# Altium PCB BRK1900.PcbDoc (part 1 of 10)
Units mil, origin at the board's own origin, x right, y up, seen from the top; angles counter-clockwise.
Board outline 8858.27 x 5905.51 mil, 10 copper layers (L1-TOP, L2-GND, L3-SIG1, L4-GND, L5-PWR, L6-PWR, L7-GND, L8-SIG2, L9-GND, L10-BOT), stack 48.824 mil thick; 507 components, 607 nets, 2498 pads, 2210 vias.
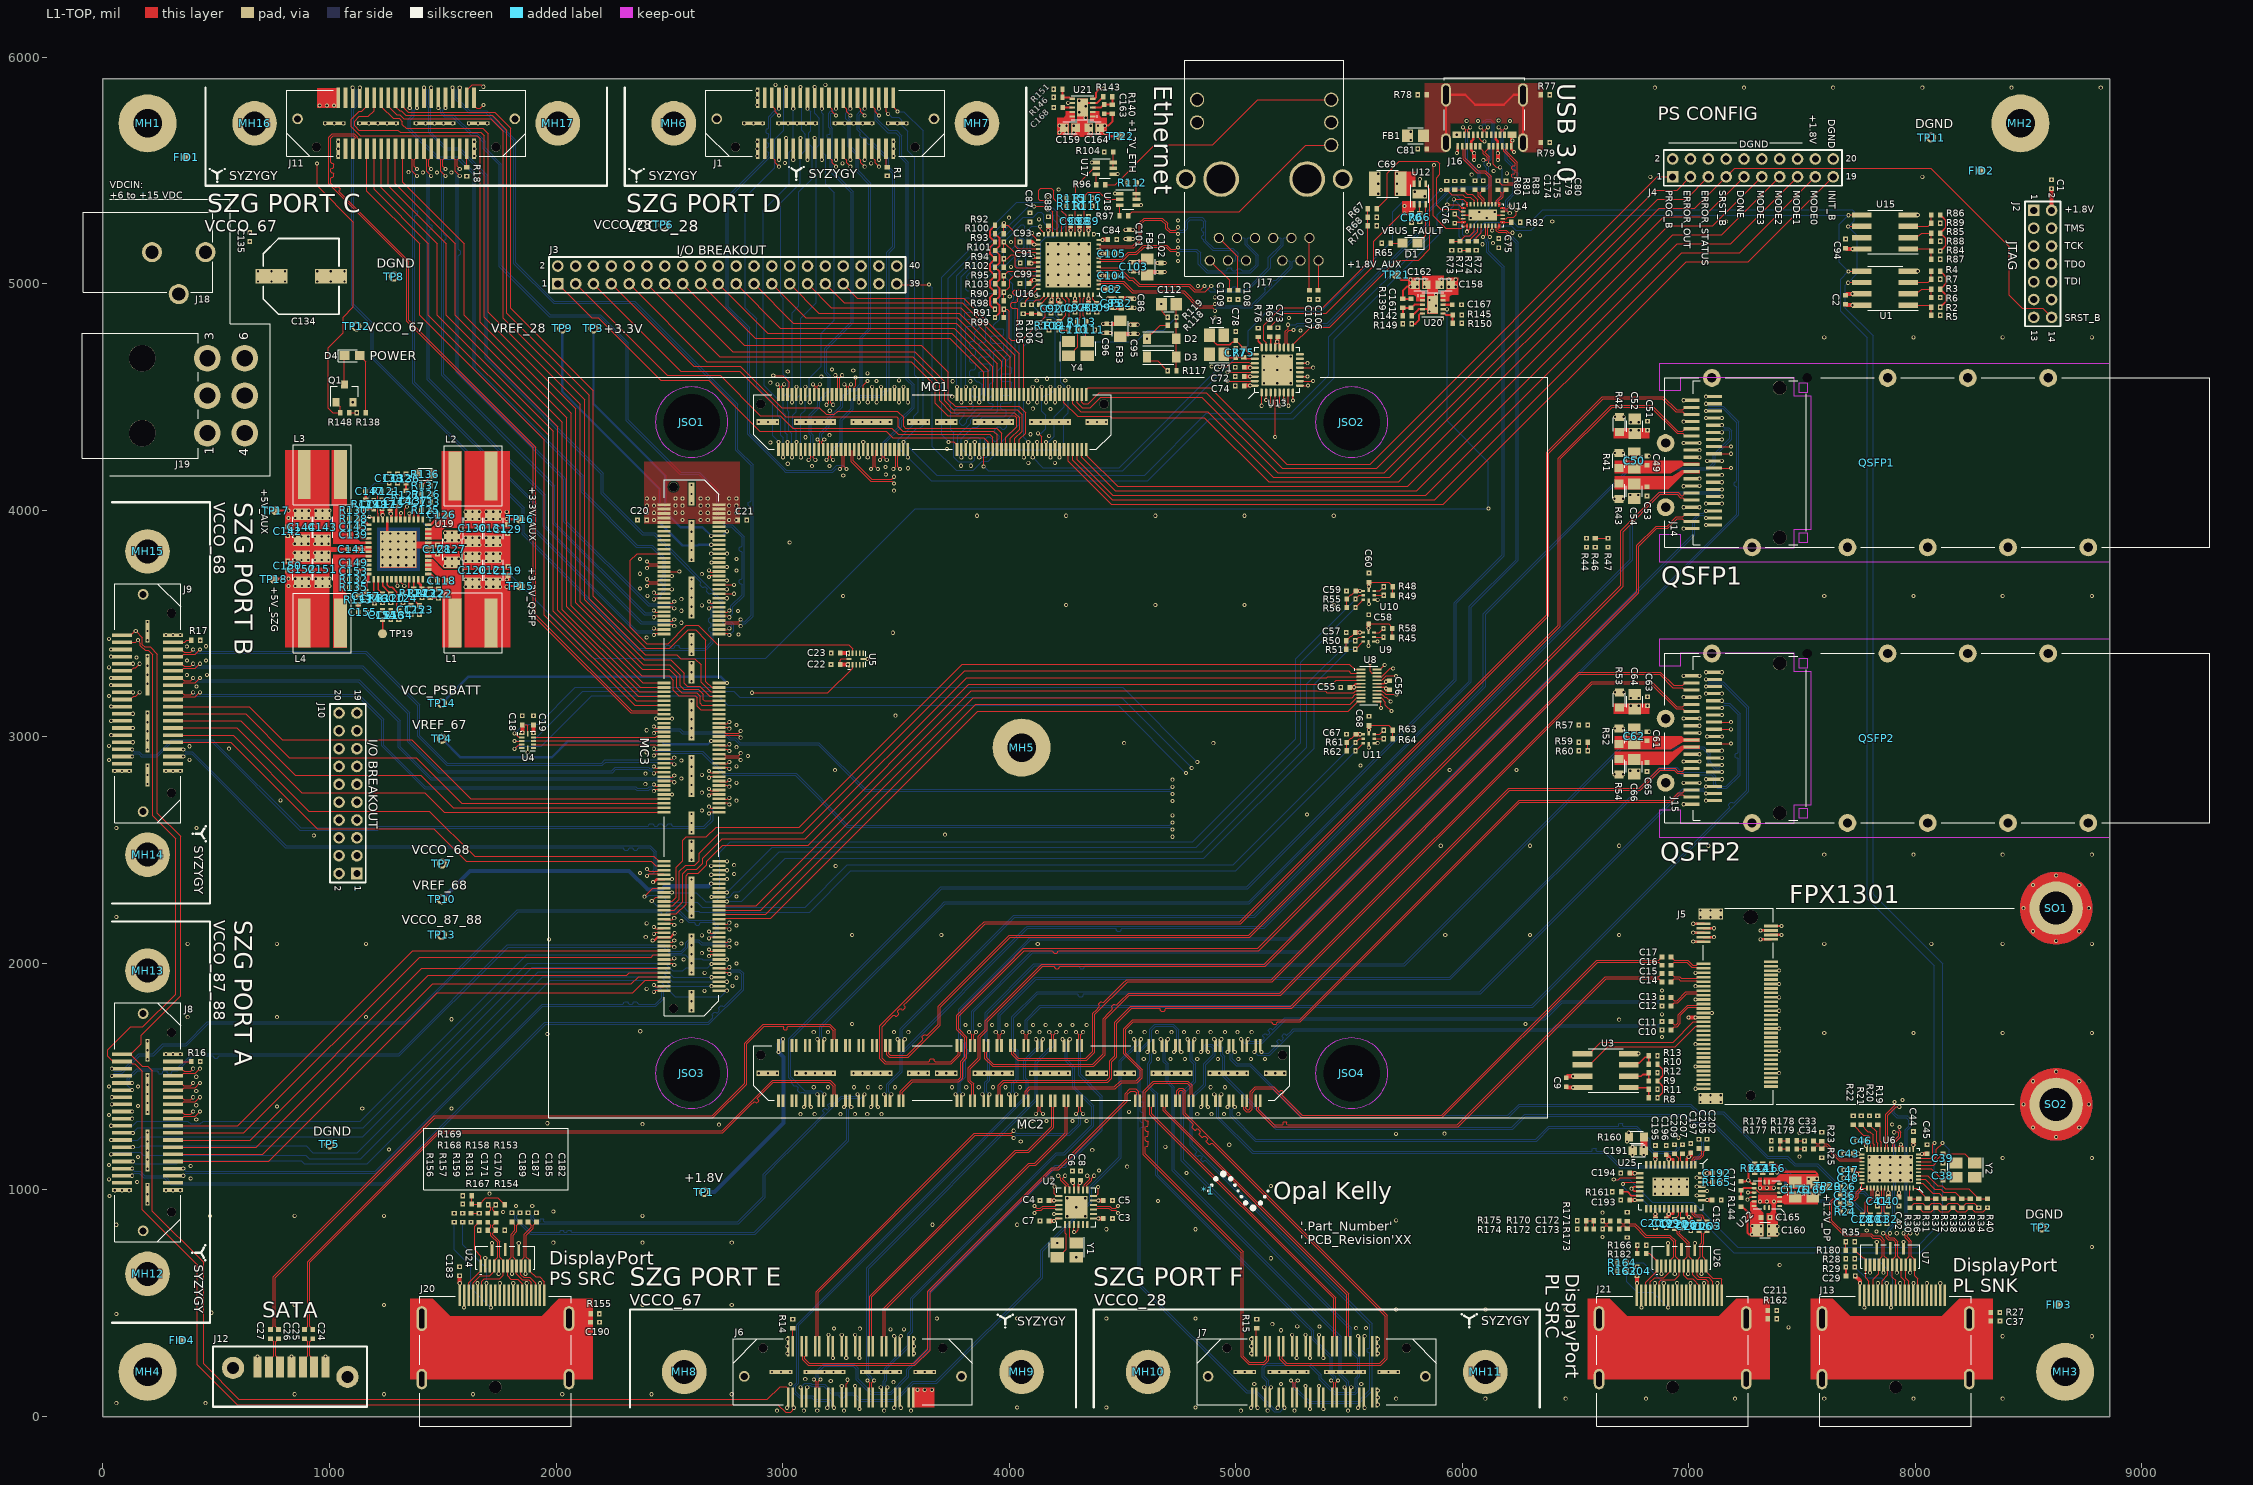
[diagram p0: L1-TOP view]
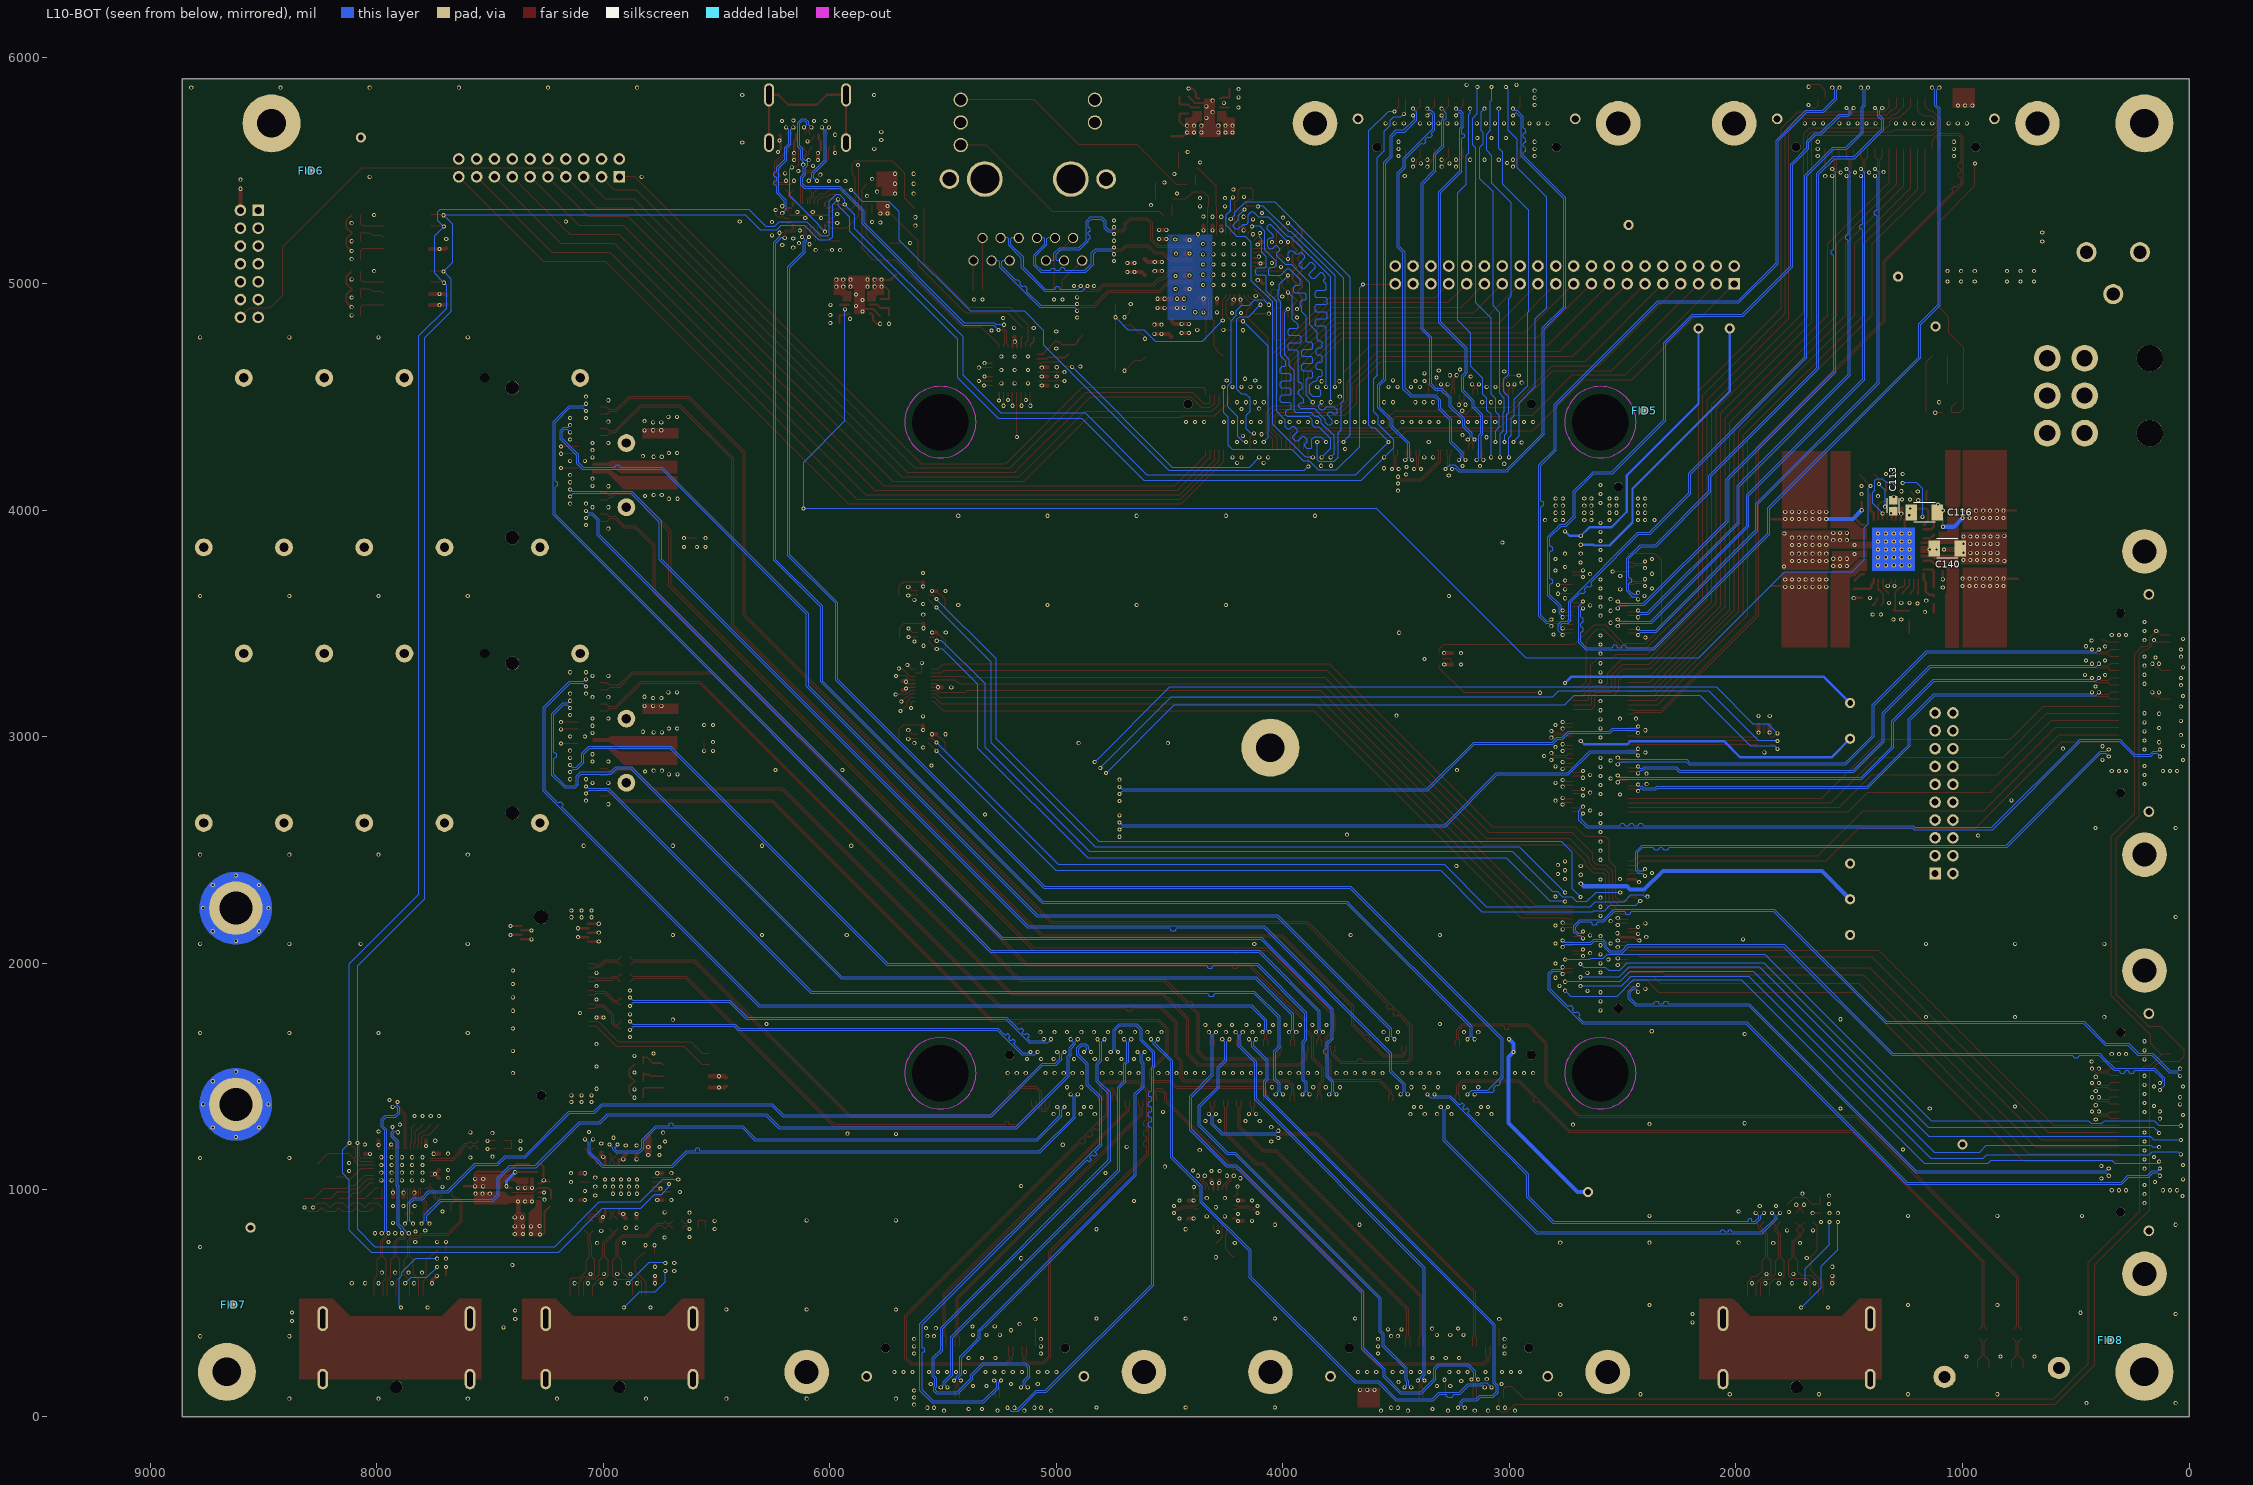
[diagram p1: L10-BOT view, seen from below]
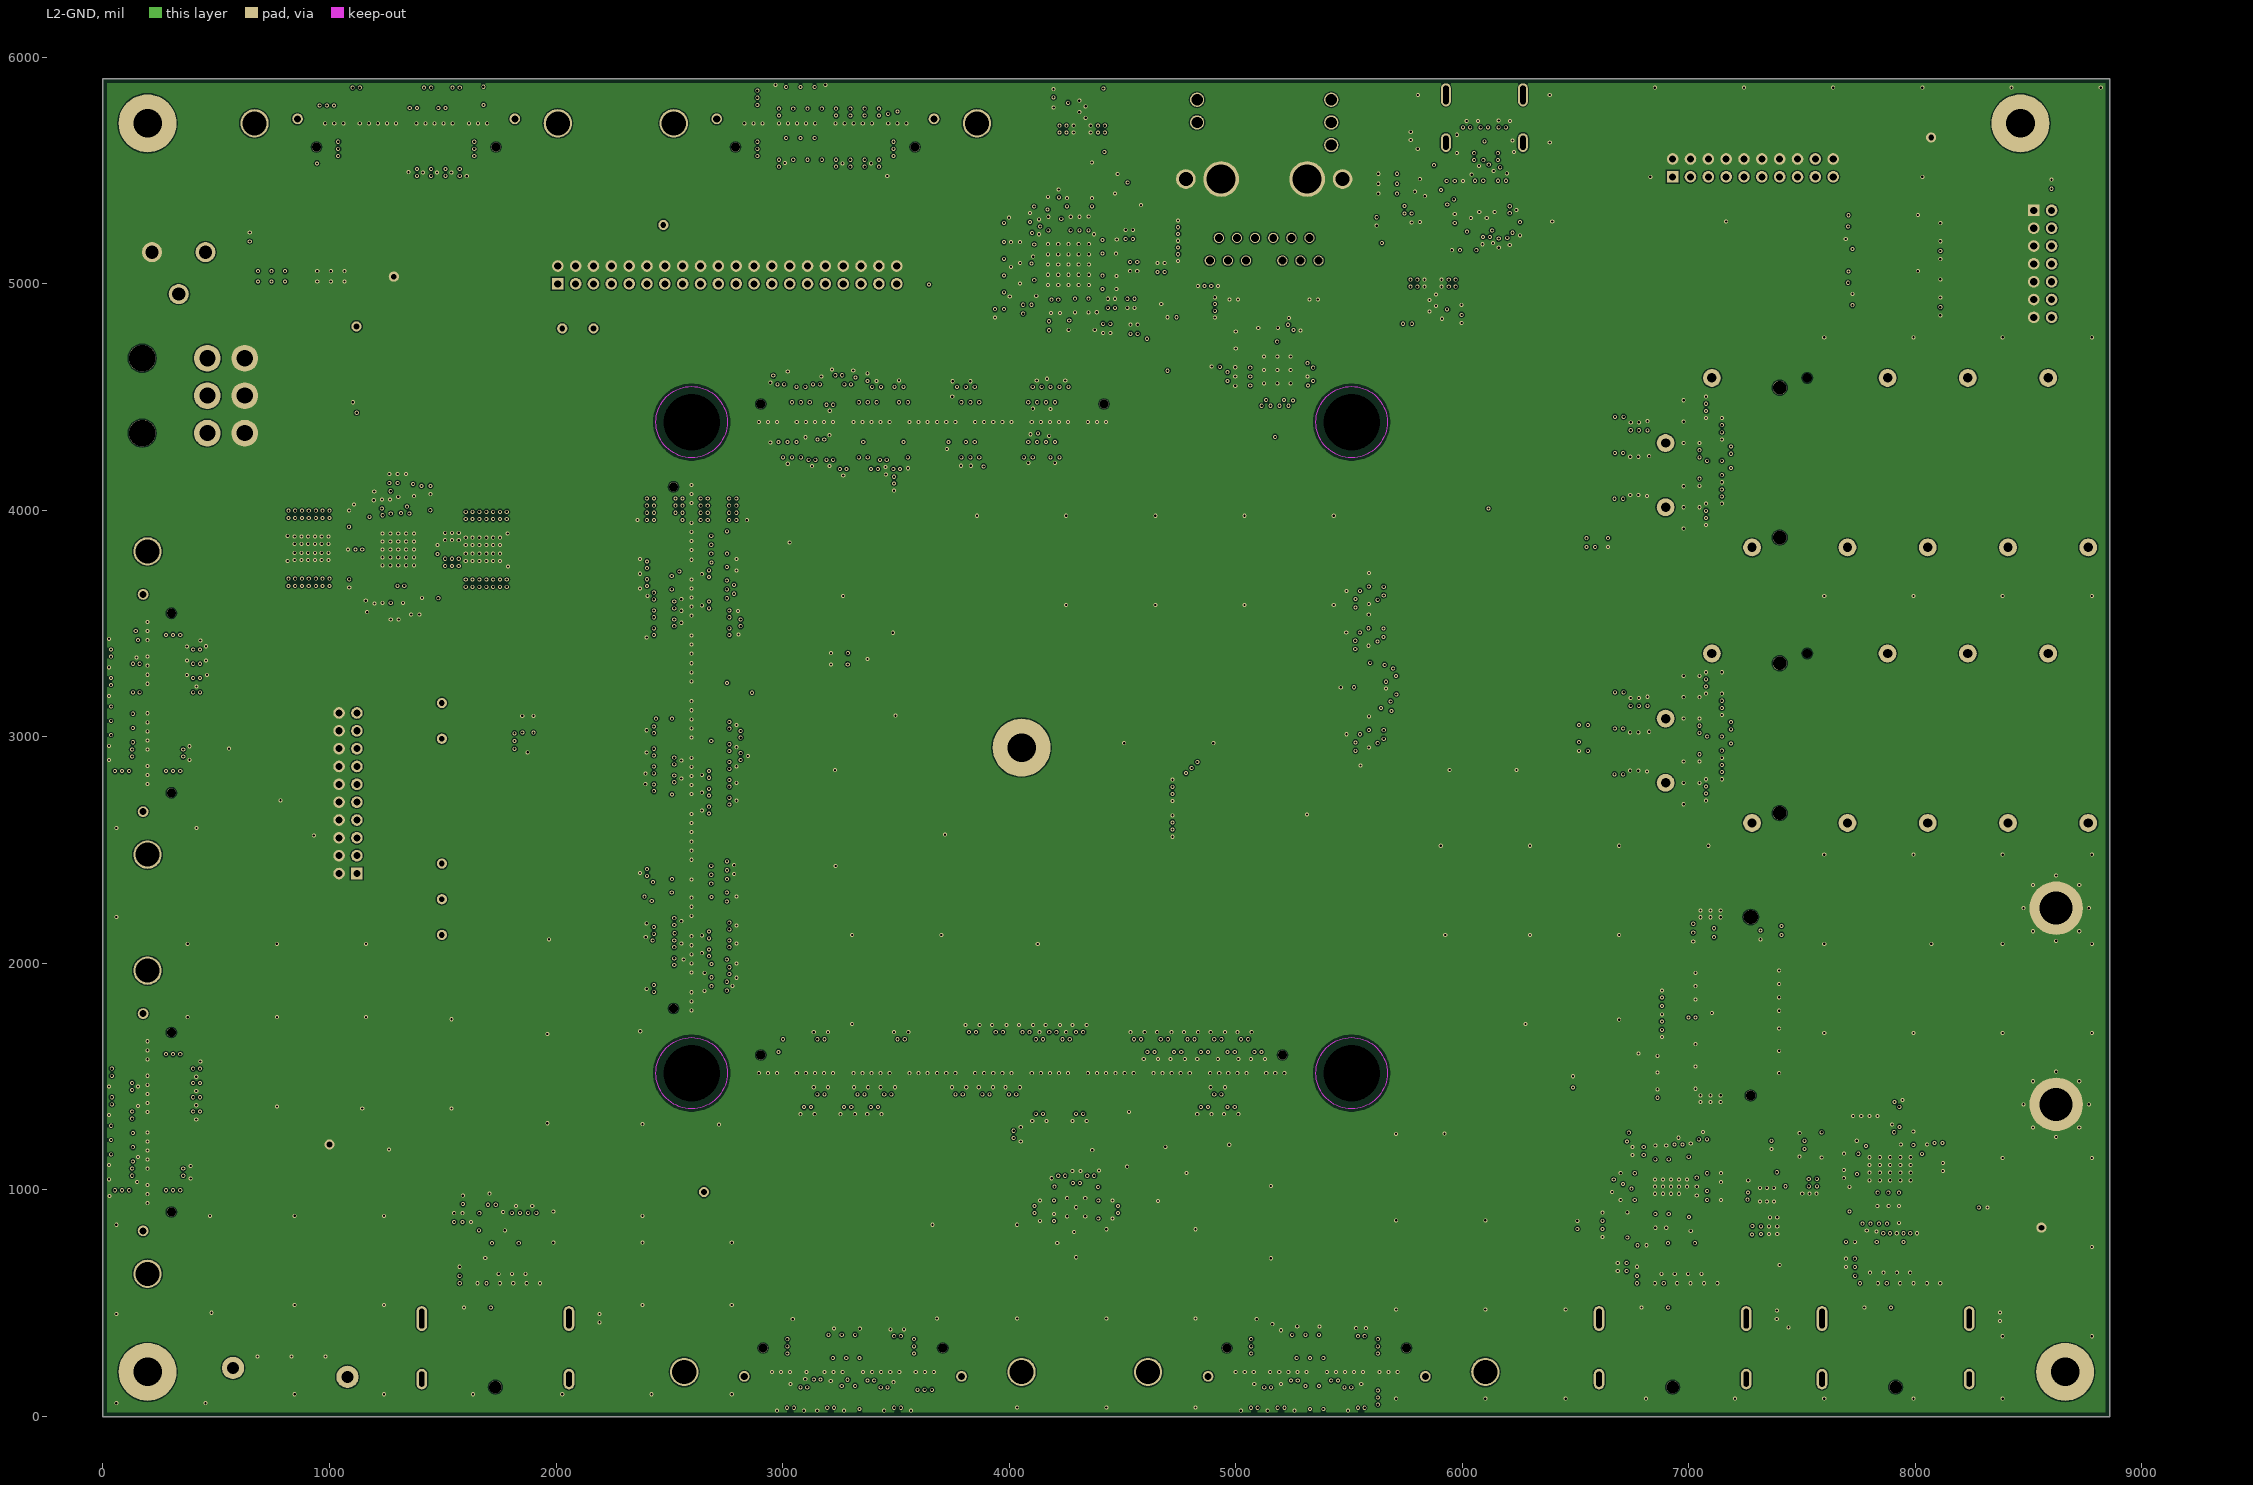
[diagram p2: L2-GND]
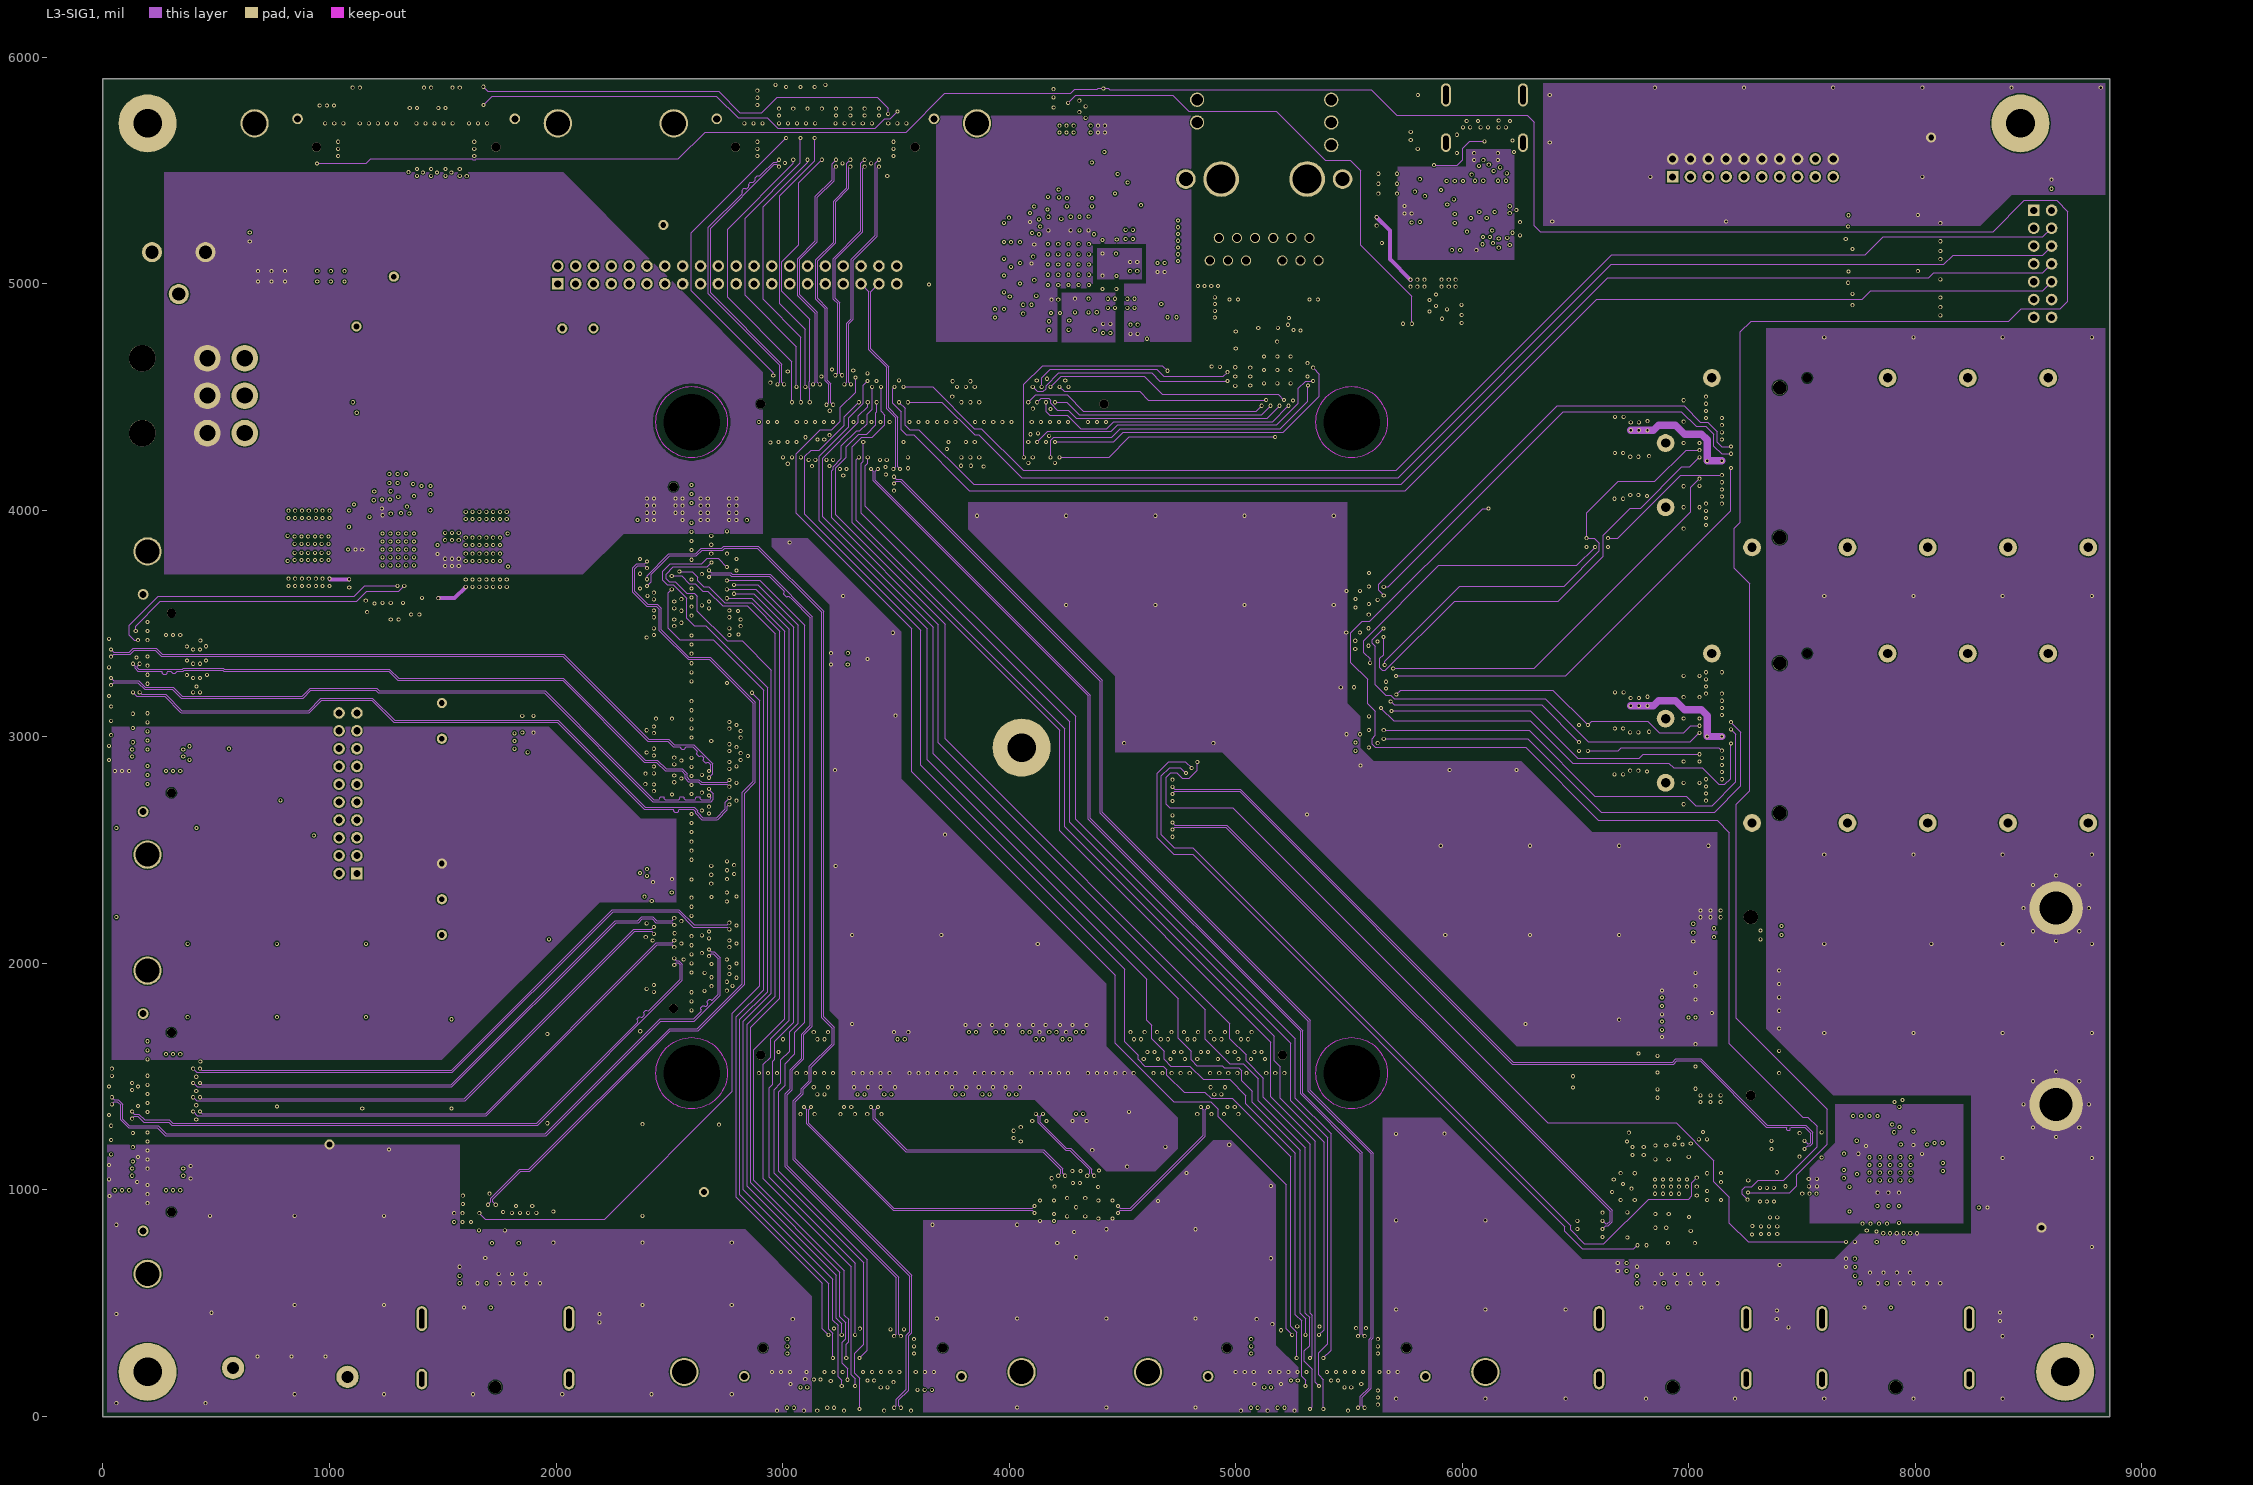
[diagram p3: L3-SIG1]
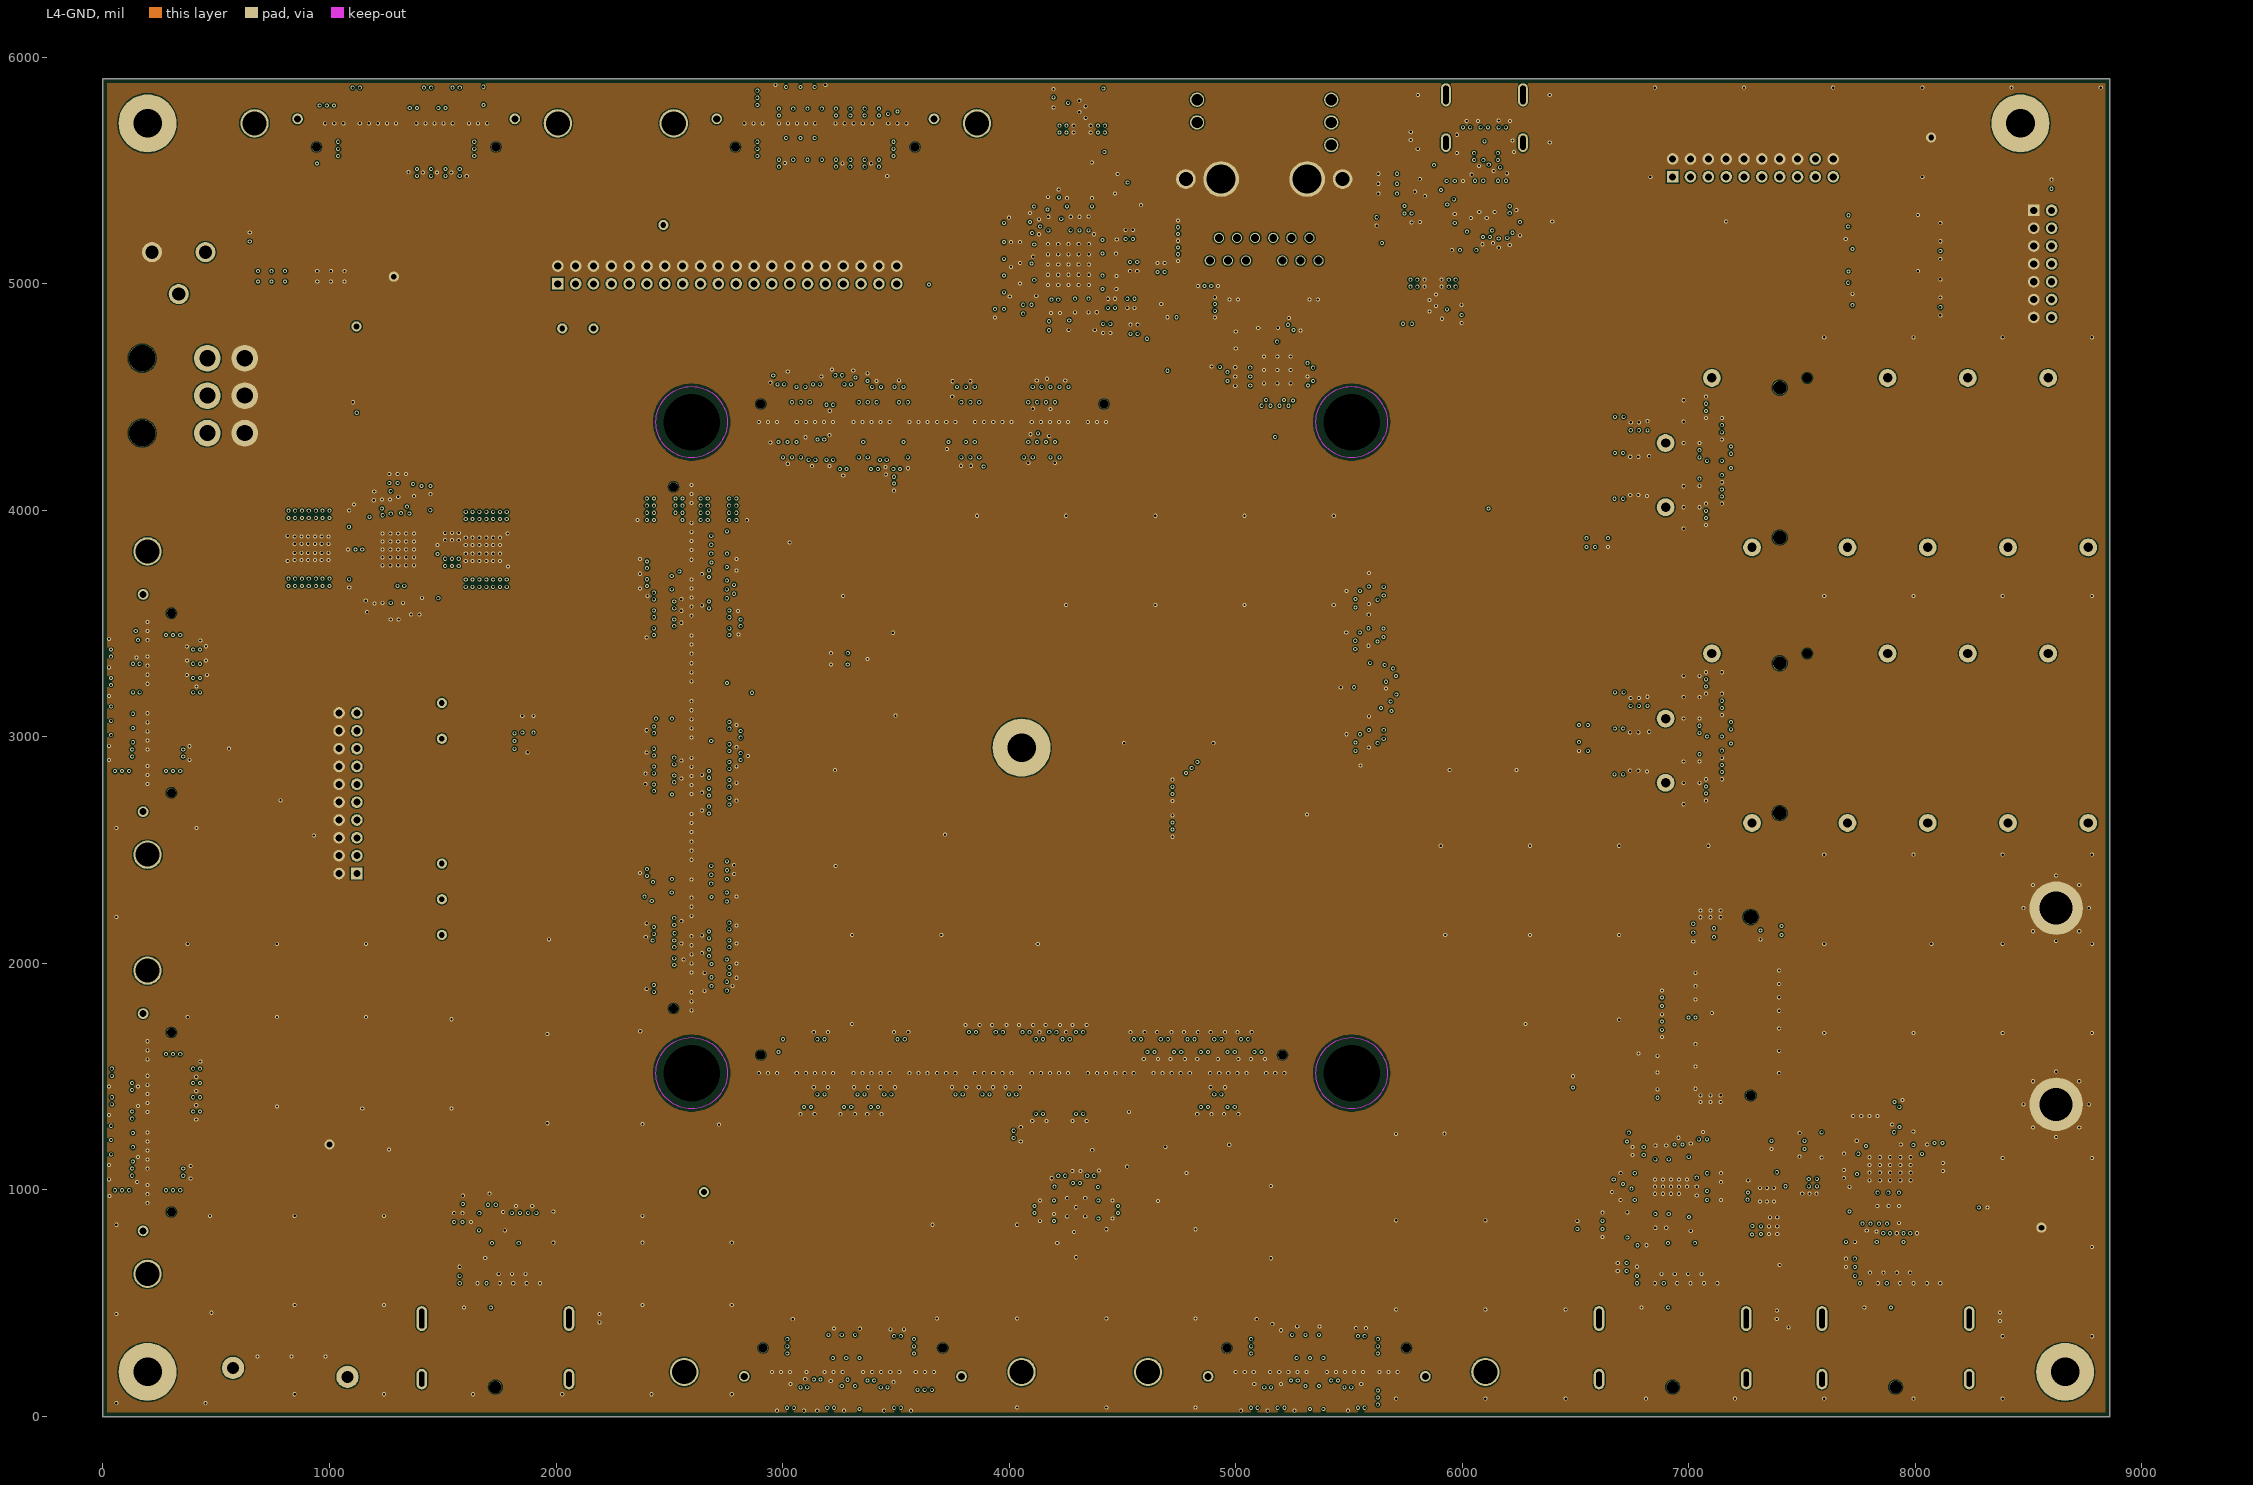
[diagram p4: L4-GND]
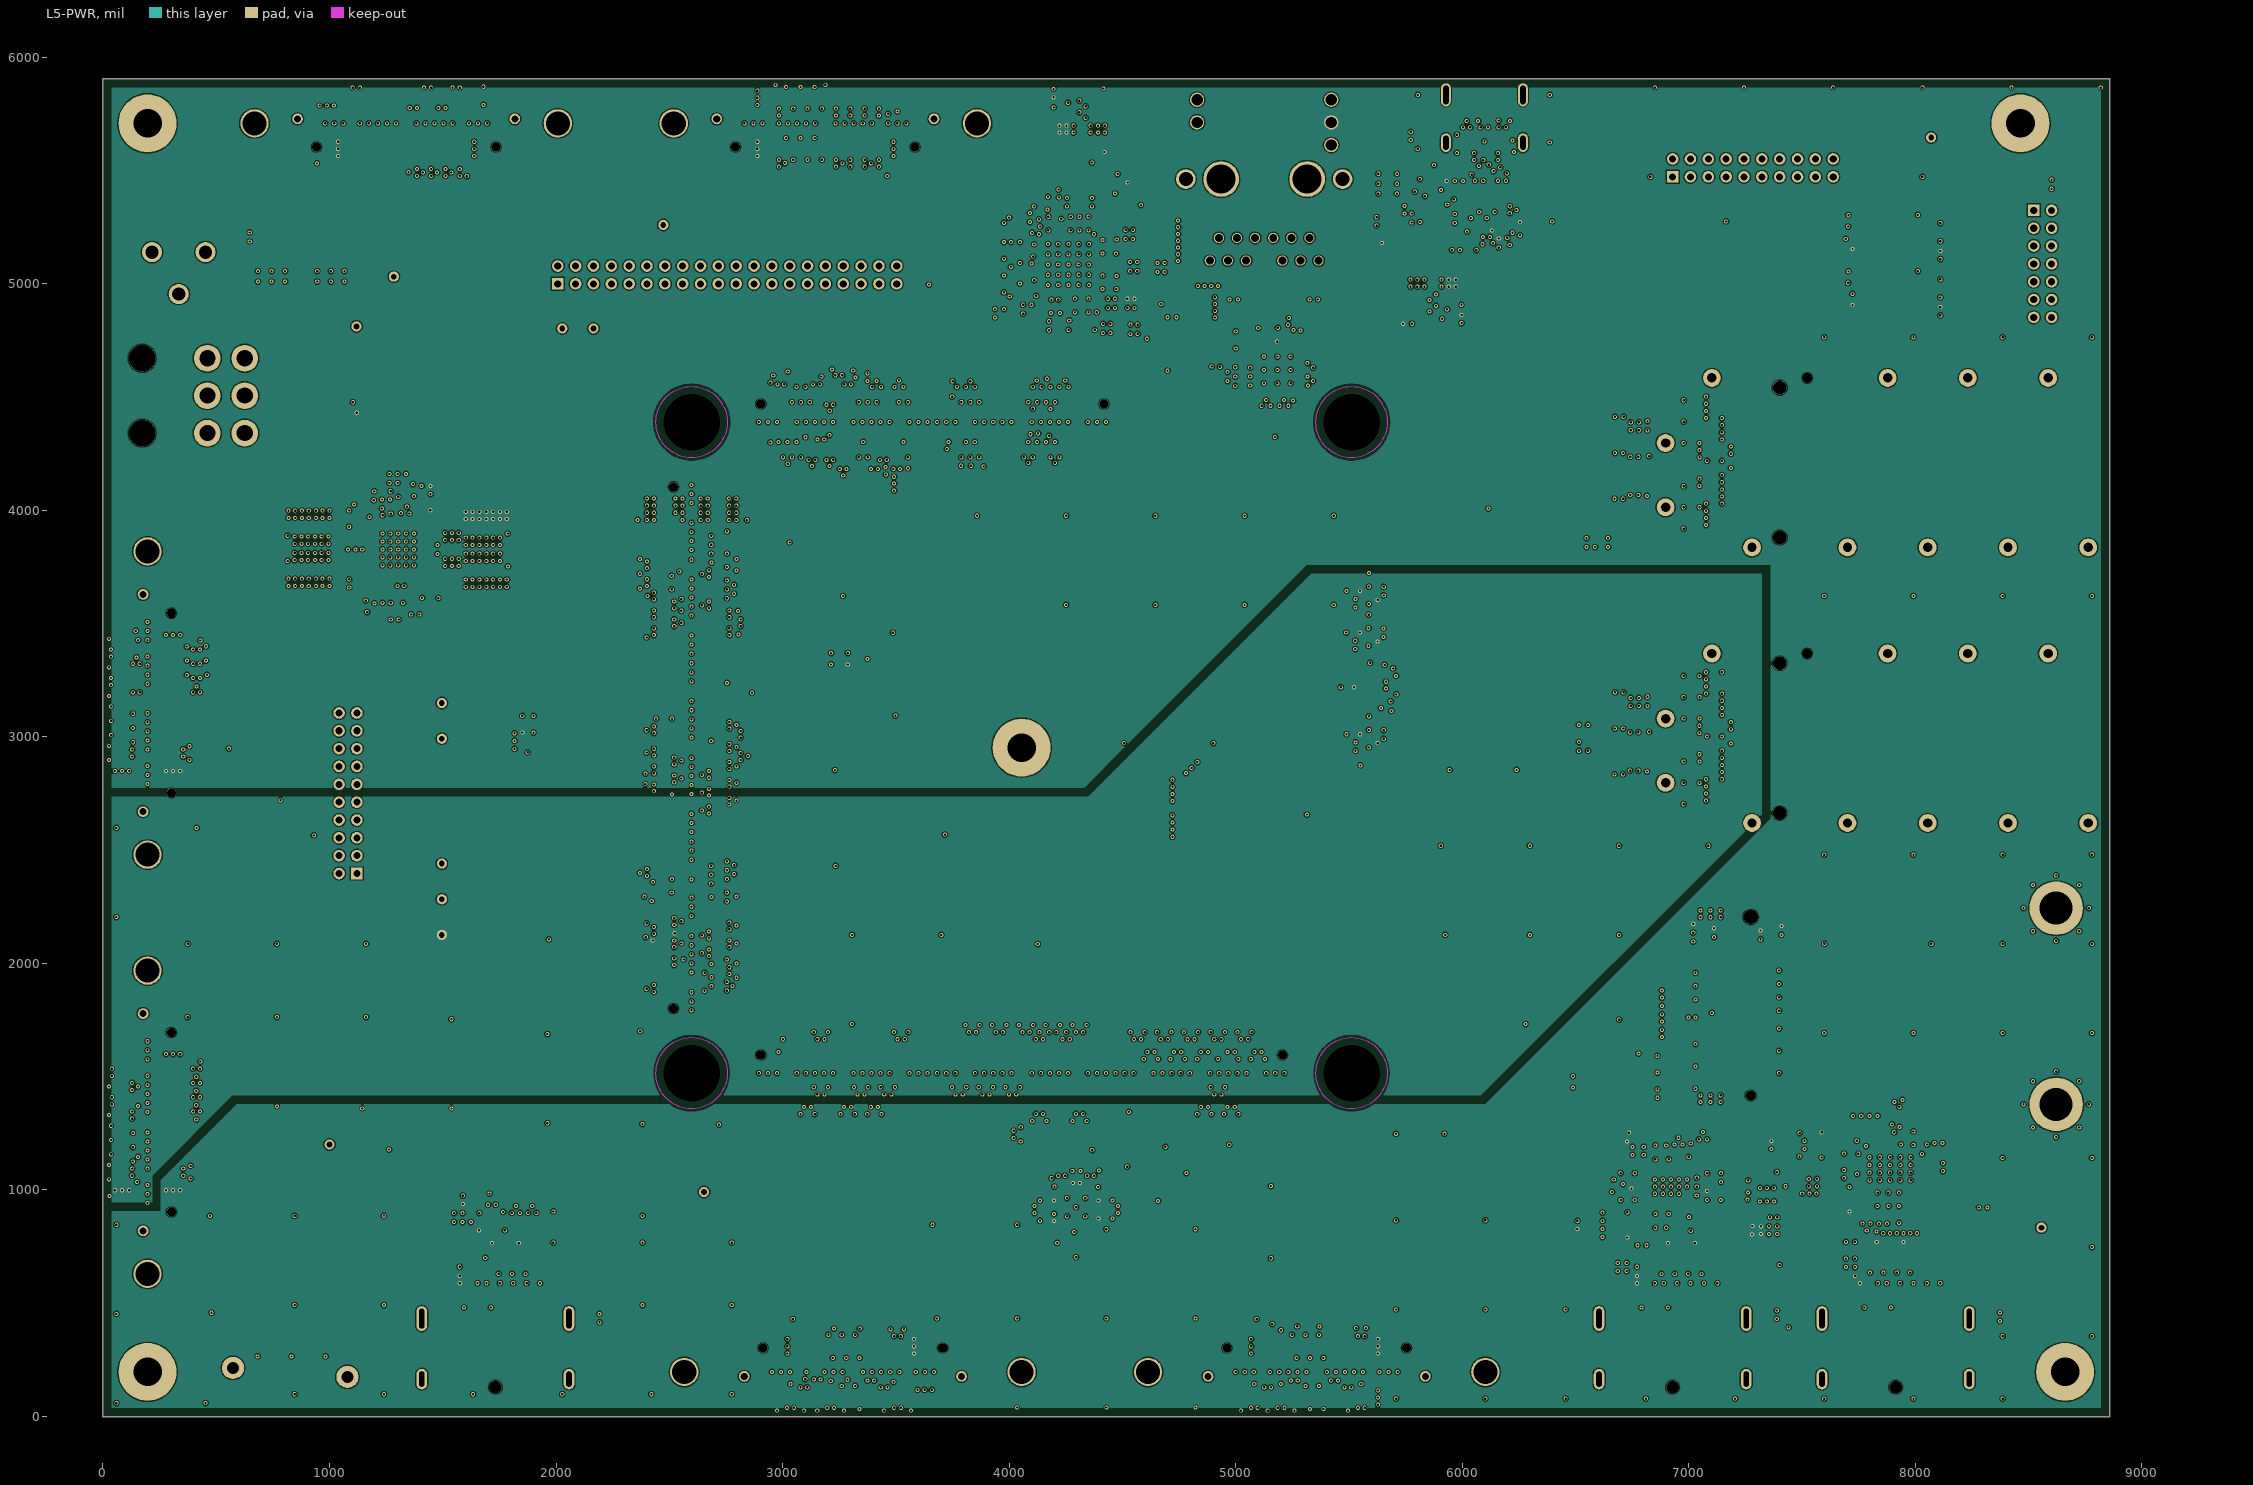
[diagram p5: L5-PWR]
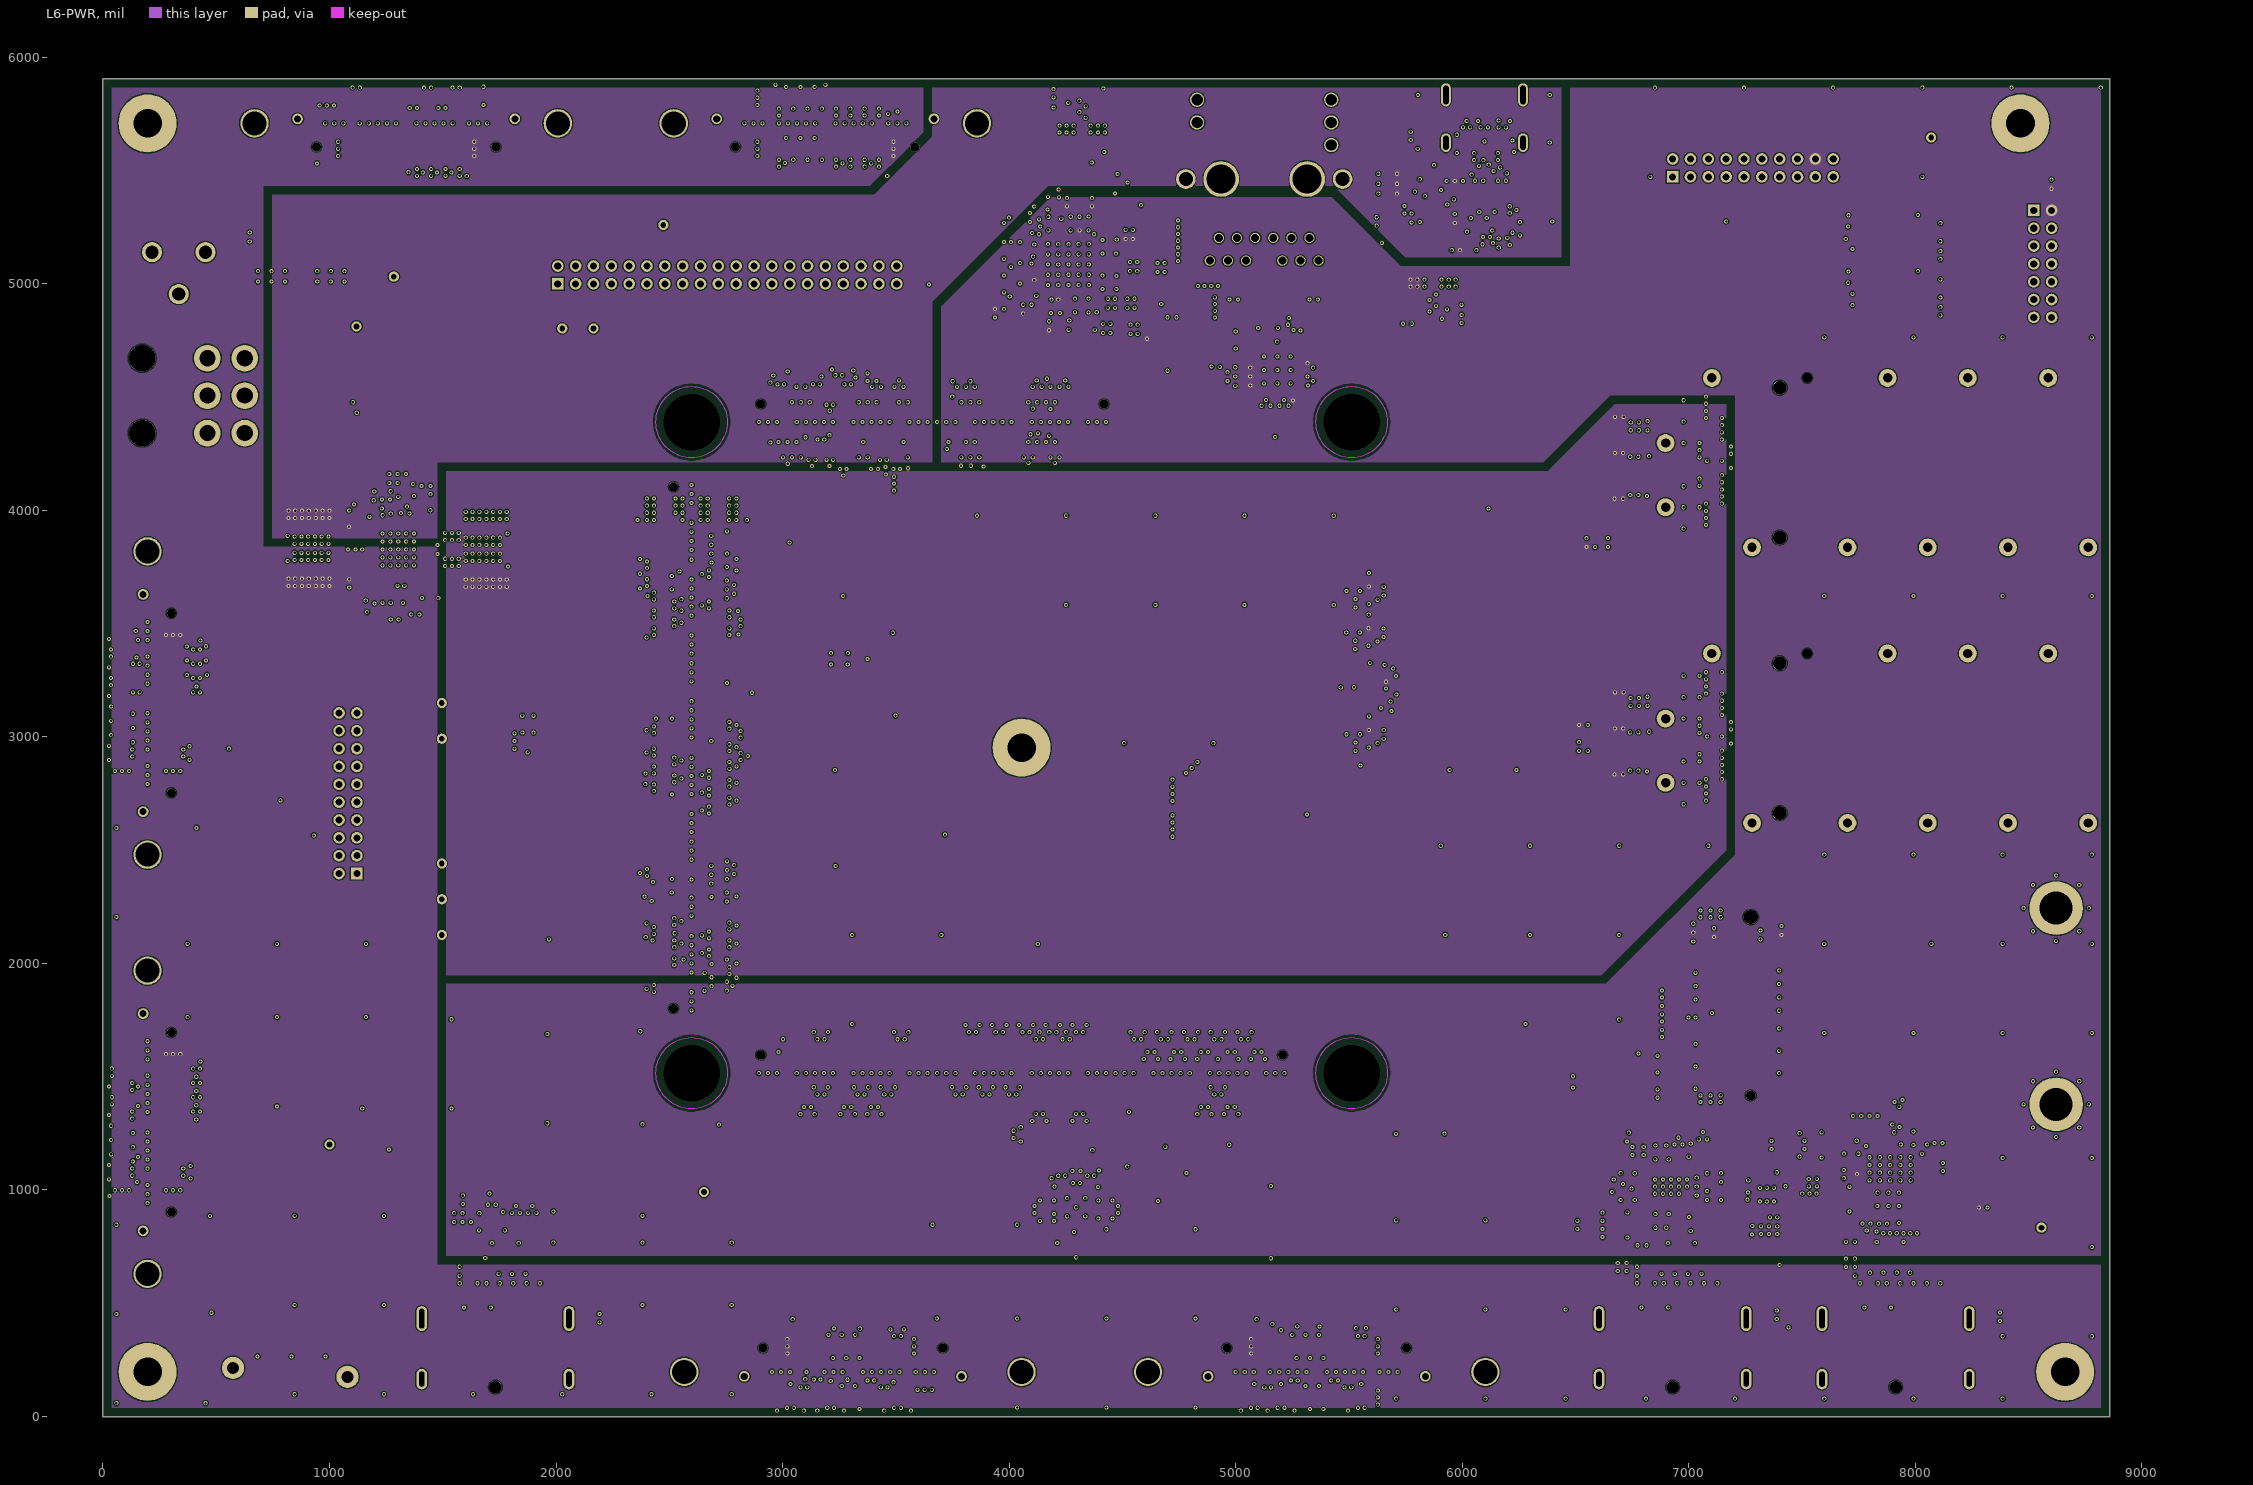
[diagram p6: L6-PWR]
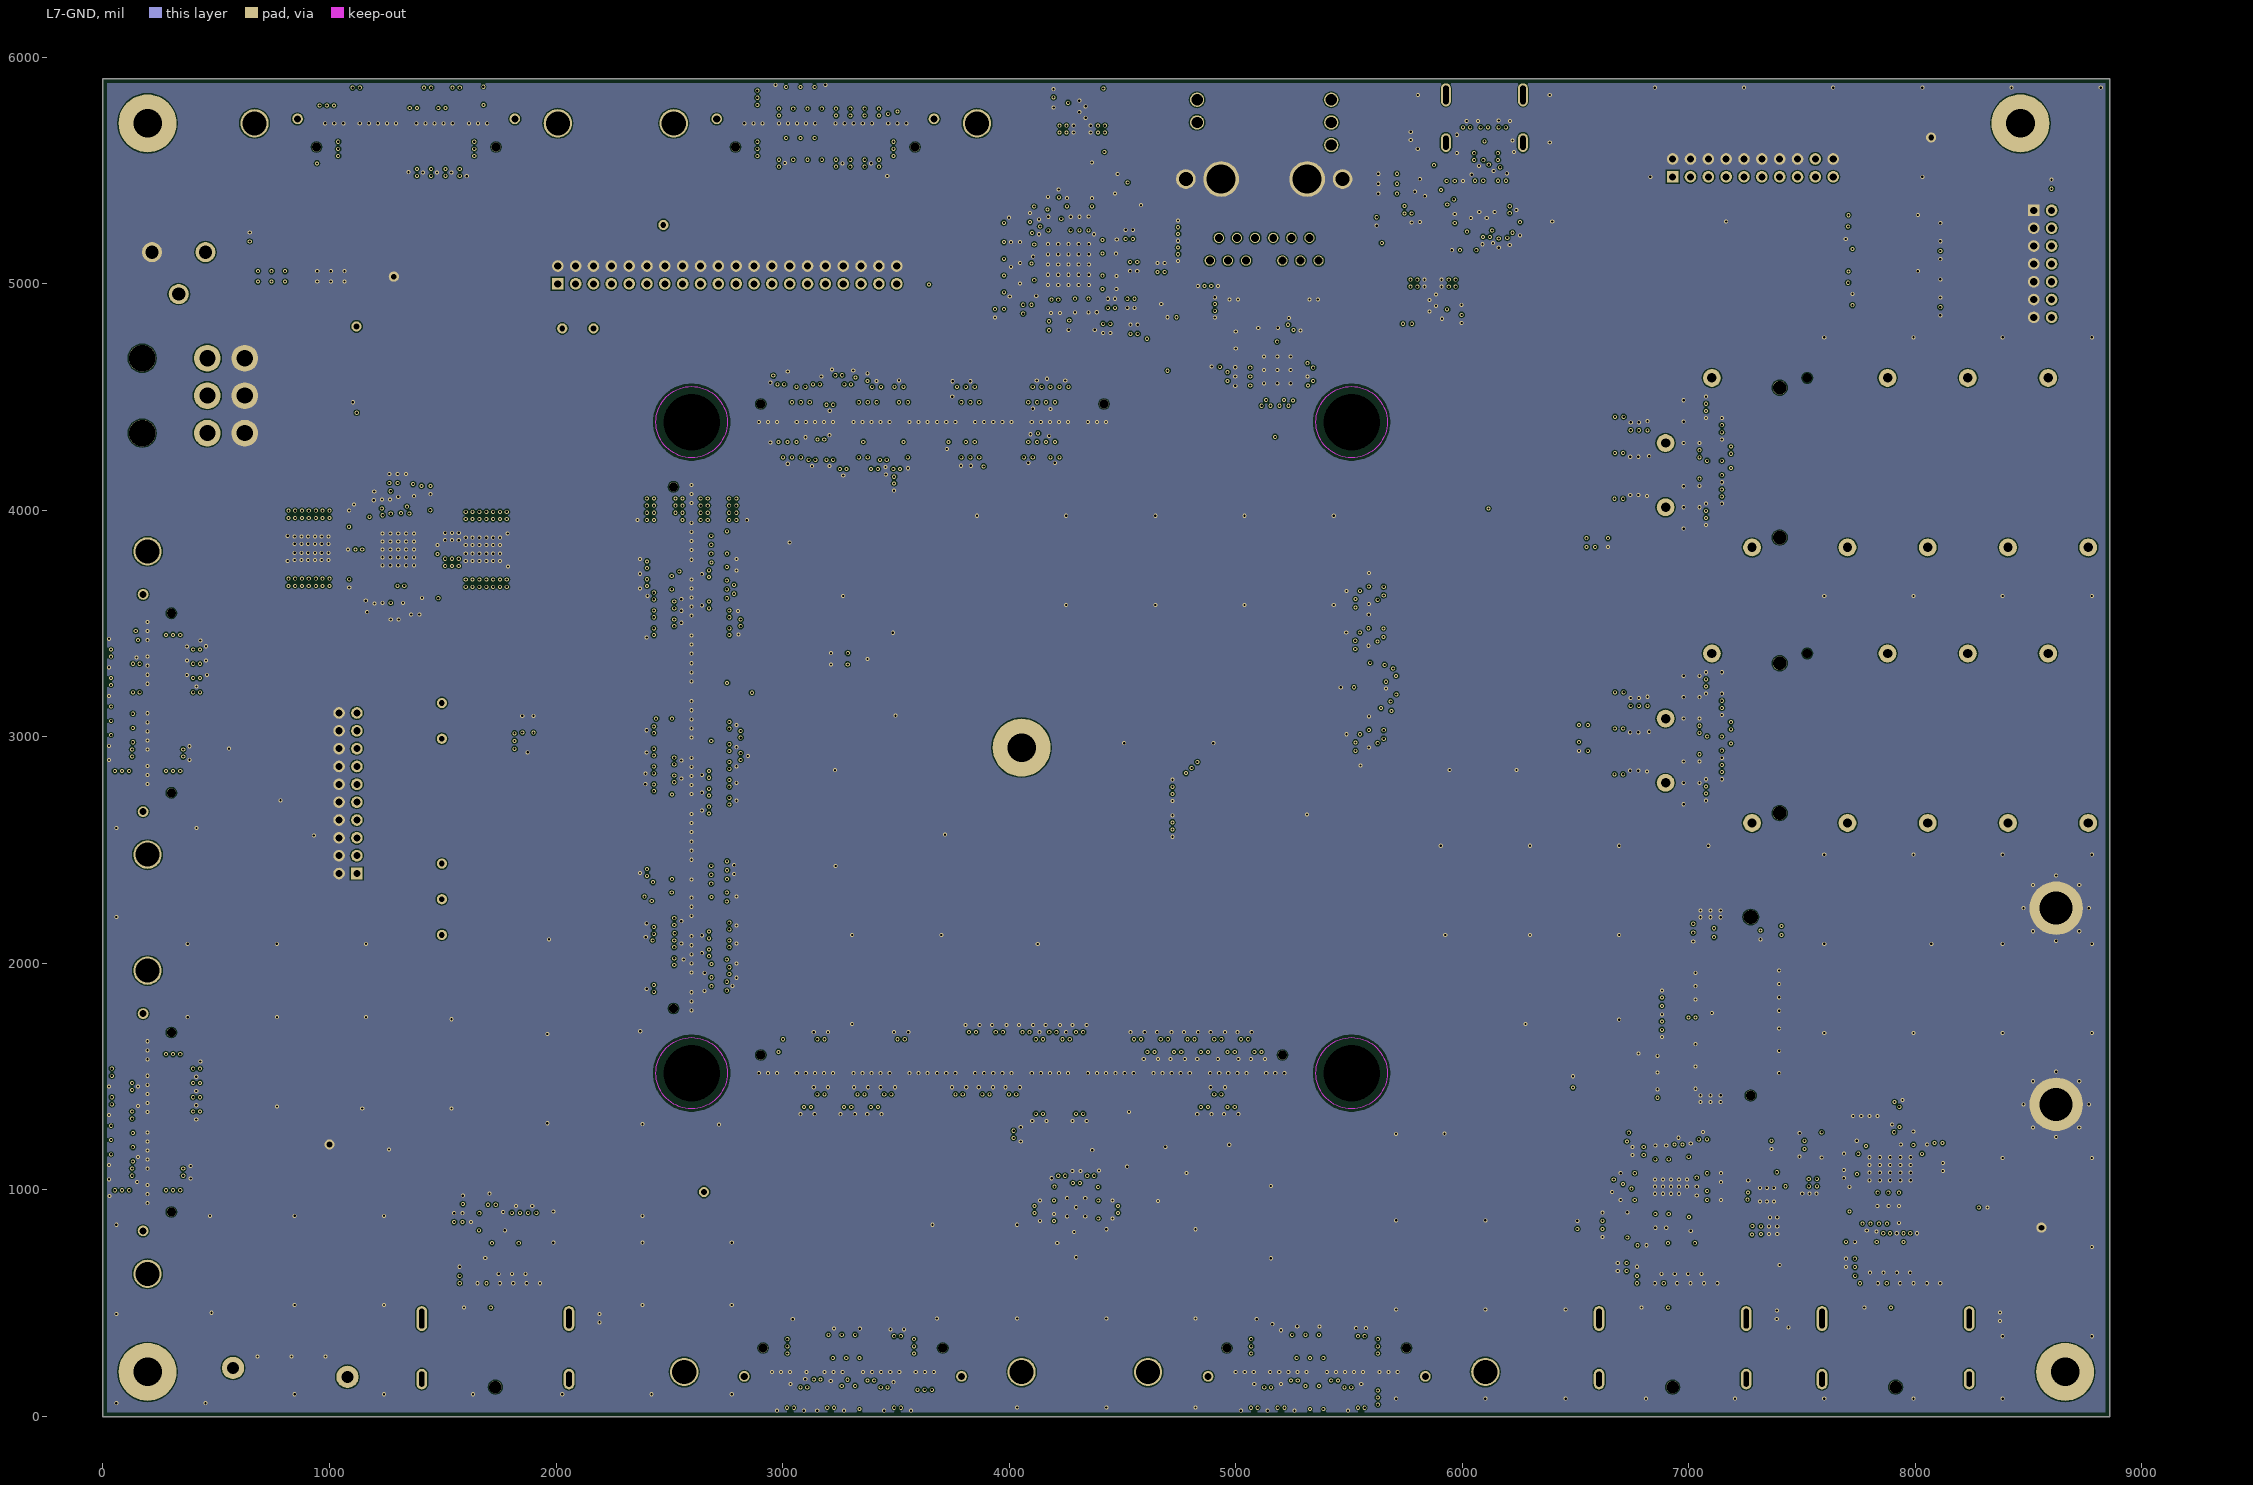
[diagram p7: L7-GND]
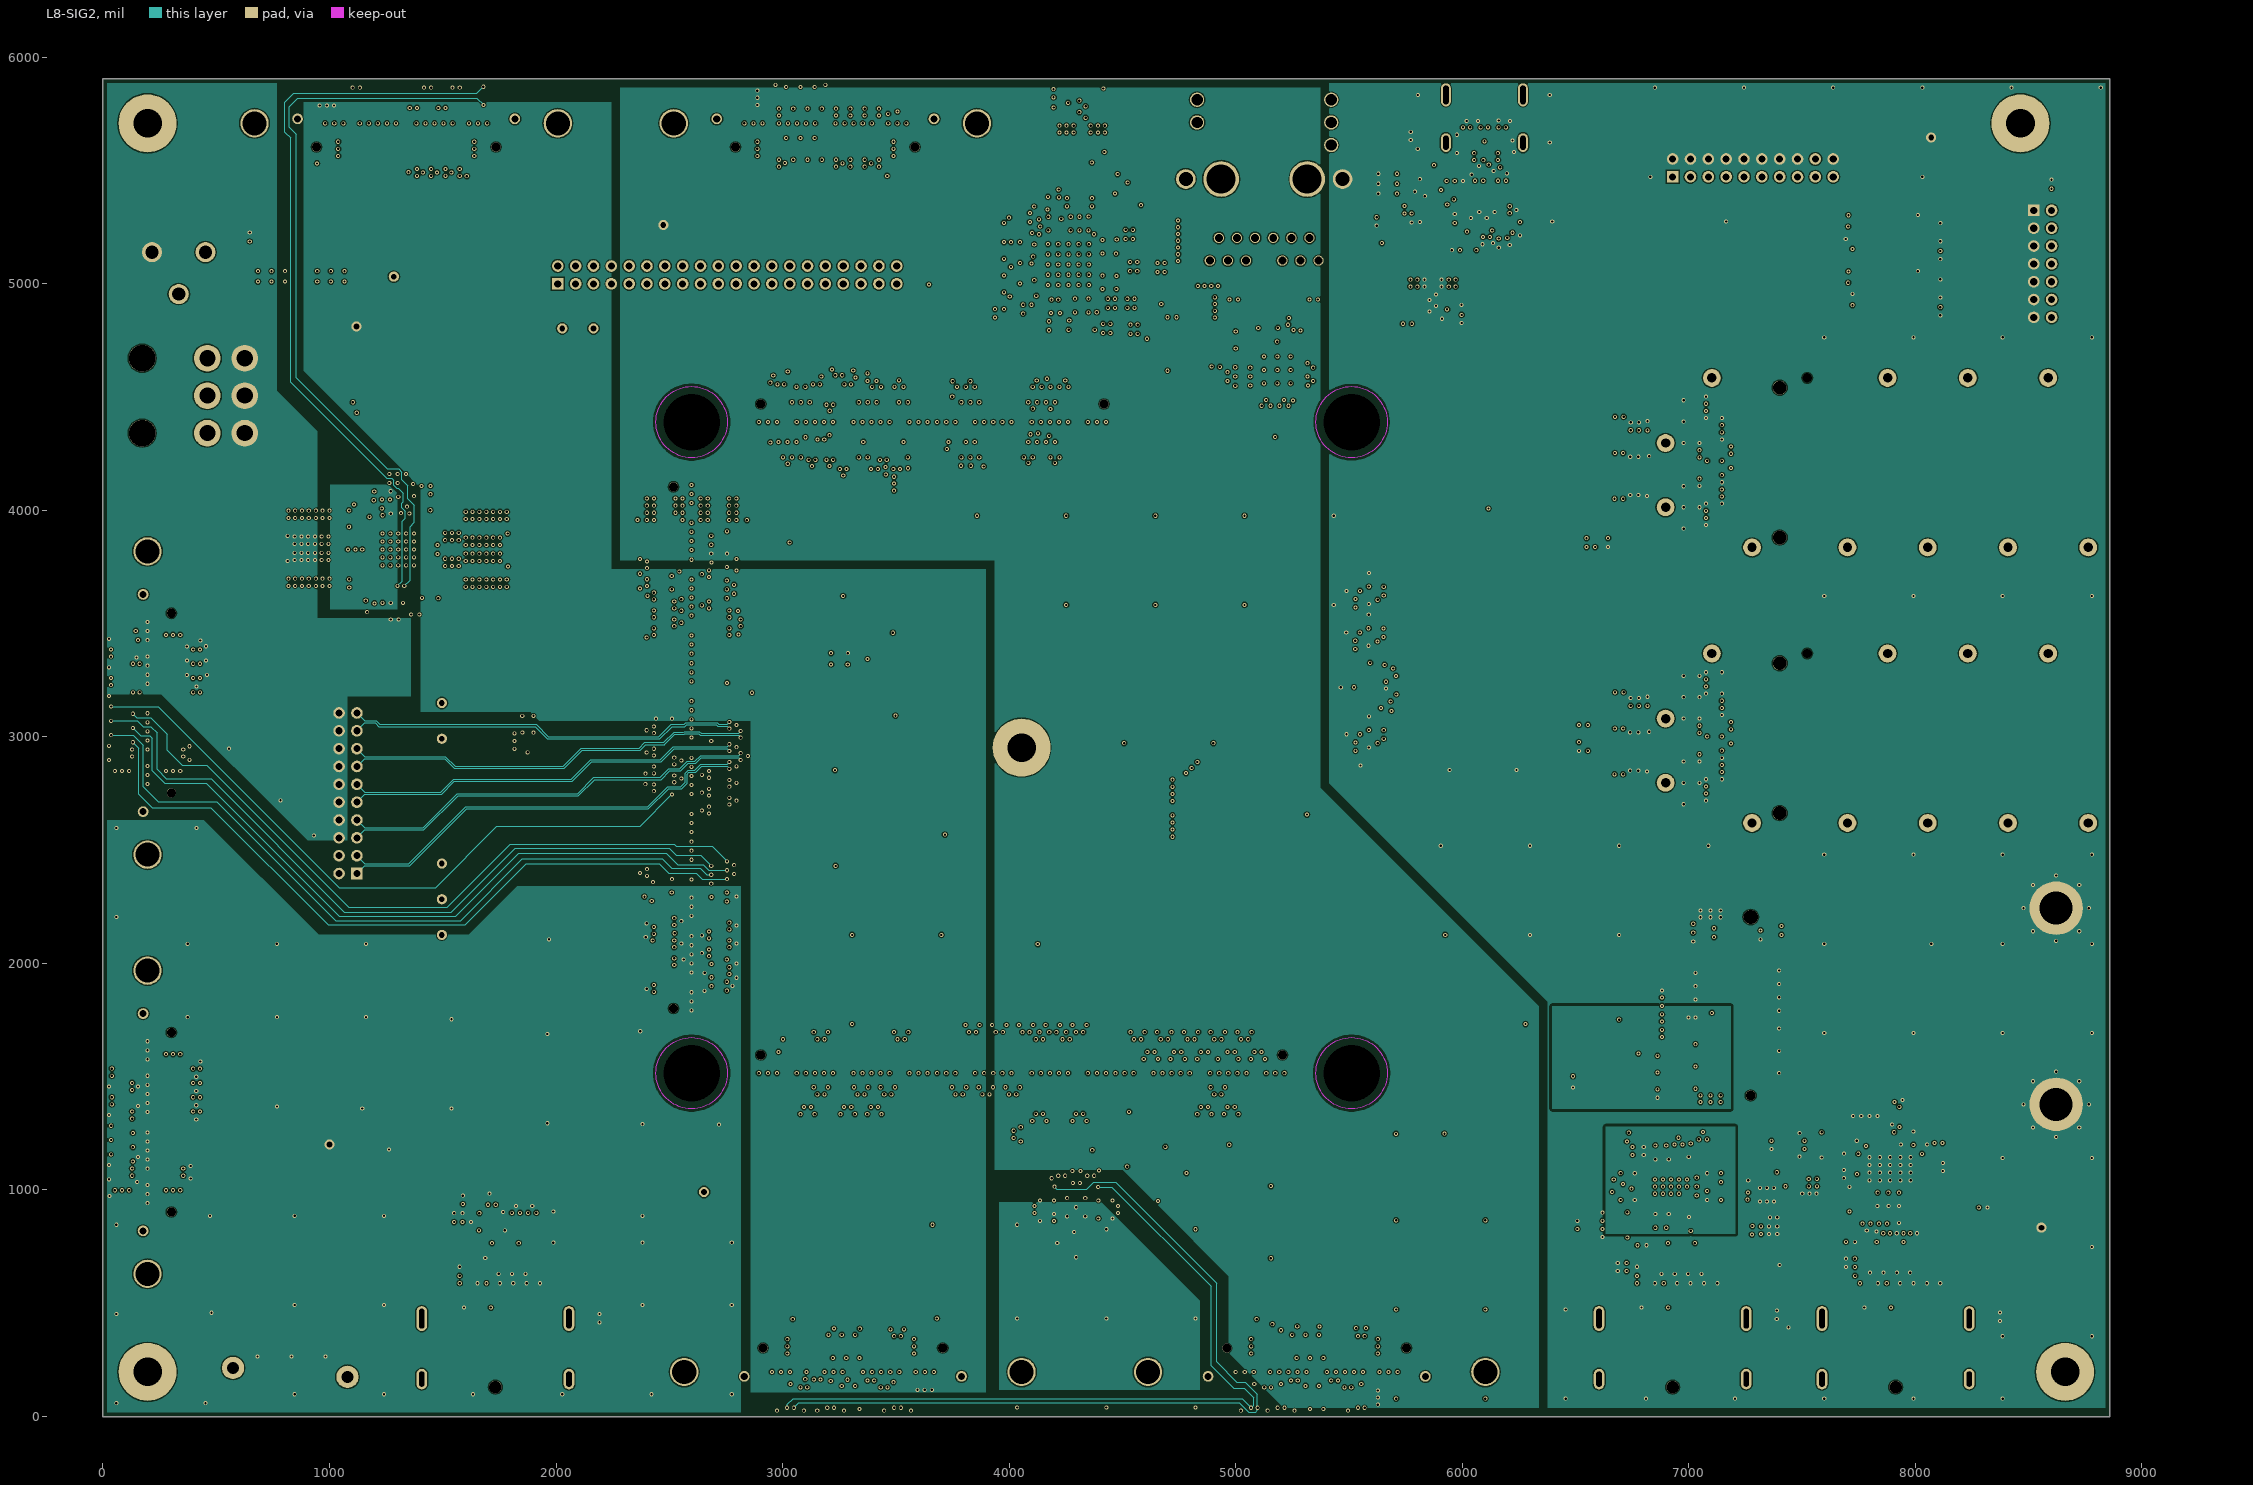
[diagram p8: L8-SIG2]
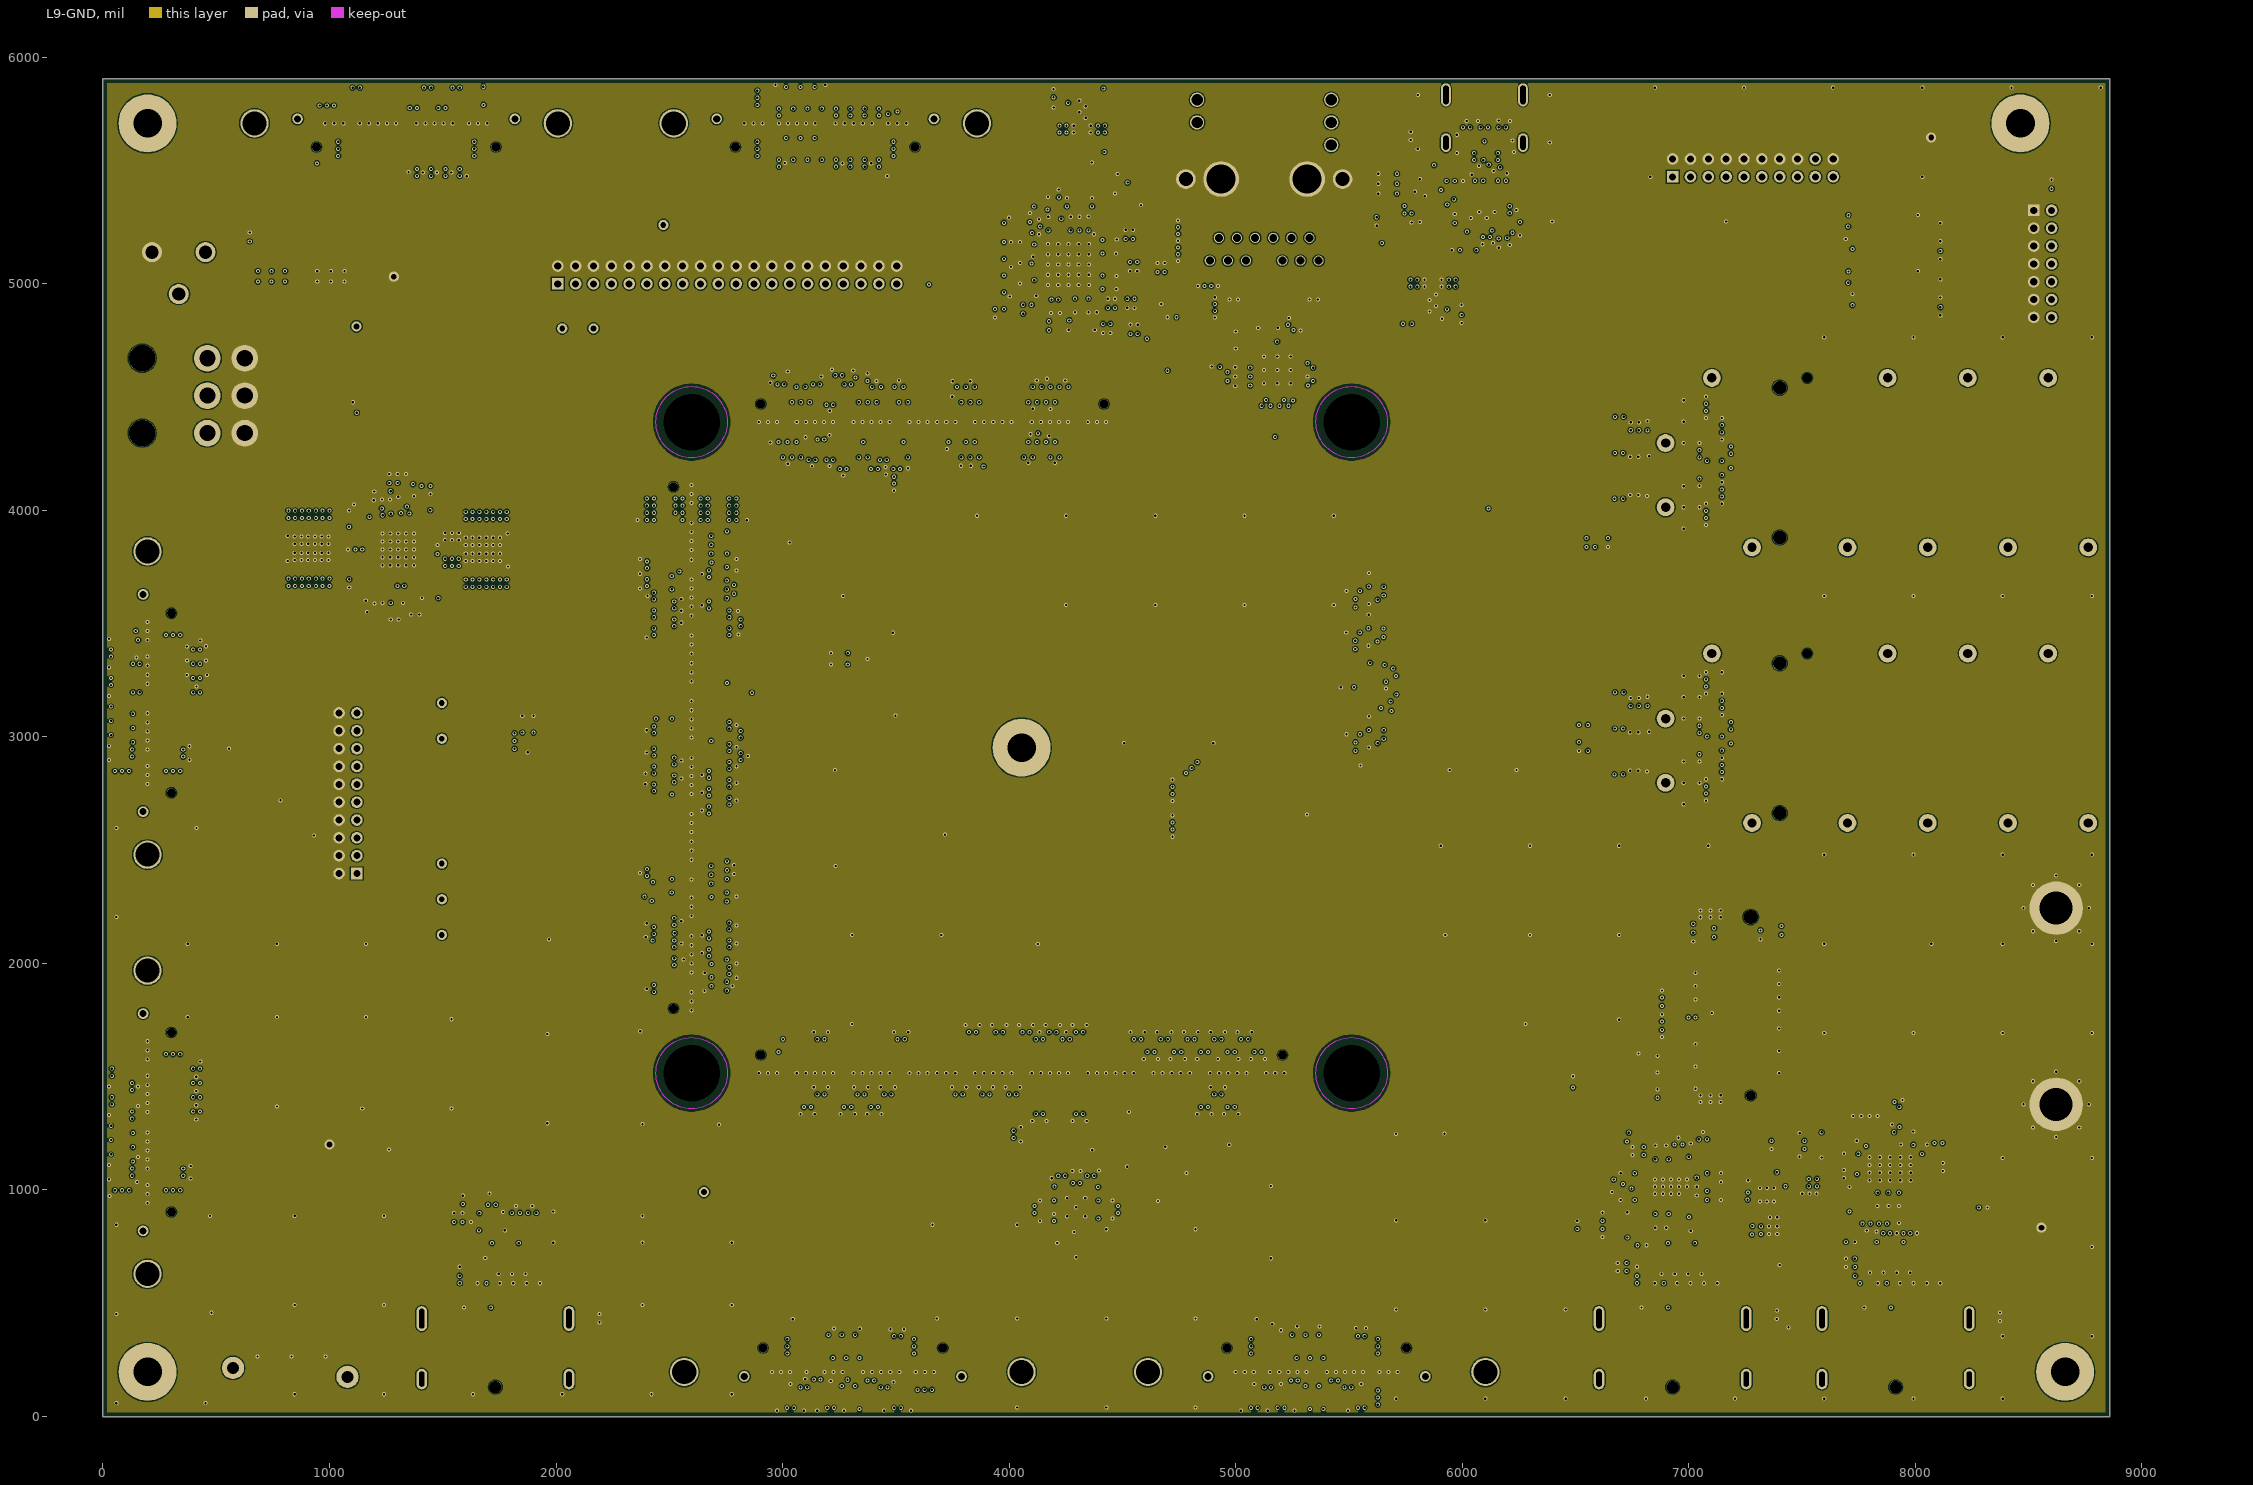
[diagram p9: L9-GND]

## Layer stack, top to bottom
Top Solder: solder mask 0.4, Solder Resist, Dk 3.5
L1-TOP: signal copper 1.4
Dielectric 1-2: prepreg 2.8, PP-006, Dk 4.1
L2-GND: signal copper 1.378
Dielectric 2-3: prepreg 2.8, PP-006, Dk 4.1
L3-SIG1: signal copper 1.378
Dielectric 3-4: prepreg 2.8, PP-006, Dk 4.1
L4-GND: signal copper 1.378
Dielectric 4-5: prepreg 2.8, PP-006, Dk 4.1
L5-PWR: signal copper 1.378
Dielectric 5-6: dielectric 12.6, FR-4, Dk 4.8
L6-PWR: signal copper 1.378
Dielectric 6-7: prepreg 2.8, PP-006, Dk 4.1
L7-GND: signal copper 1.378
Dielectric 7-8: prepreg 2.8, PP-006, Dk 4.1
L8-SIG2: signal copper 1.378
Dielectric 8-9: prepreg 2.8, PP-006, Dk 4.1
L9-GND: signal copper 1.378
Dielectric 9-10: prepreg 2.8, PP-006, Dk 4.1
L10-BOT: signal copper 1.4
Bottom Solder: solder mask 0.4, Solder Resist, Dk 3.5

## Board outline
0,0 8858.27,0 8858.27,5905.51 0,5905.51

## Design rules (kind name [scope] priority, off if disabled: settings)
Clearance [All] p1: gap=5 ignorepadtopadclearanceinfootprint=FALSE except(0: Arc-Hole Track-Hole SMDPad-Hole THPad-Hole Via-Hole Fill-Hole Poly-Hole Region-Hole Text-Hole; 3.5: Track-Track; 4: Track-SMDPad Track-THPad Track-Via; 5.5: SMDPad-SMDPad; 6: SMDPad-THPad; 7: THPad-THPad Fill-Fill Fill-Poly Fill-Region Fill-Text Region-Region; 12: Poly-Poly Poly-Region)
DiffPairsRouting DiffPairsRouting_100ohm [InDifferentialPairClass('DiffPair_100ohm')] p1: maxlimit=5.85 minlimit=1 mostfreqgap=1 toplayer_mingap=5.7 toplayer_maxgap=5.7 toplayer_prefgap=5.7 toplayer_minwidth=3.3 toplayer_maxwidth=3.3 toplayer_prefwidth=3.3 midlayer1_mingap=5.85 midlayer1_prefgap=5.85 midlayer1_minwidth=3.15 midlayer1_maxwidth=3.15 midlayer1_prefwidth=3.15 midlayer2_maxgap=1 midlayer2_minwidth=1 midlayer2_maxwidth=1 midlayer2_prefwidth=1 midlayer3_maxgap=1 midlayer3_minwidth=1 midlayer3_maxwidth=1 midlayer3_prefwidth=1 midlayer4_maxgap=1 midlayer4_minwidth=1 midlayer4_maxwidth=1 midlayer4_prefwidth=1 midlayer5_maxgap=1 midlayer5_minwidth=1 midlayer5_maxwidth=1 midlayer5_prefwidth=1 midlayer6_maxgap=1 midlayer6_minwidth=1 midlayer6_maxwidth=1 midlayer6_prefwidth=1 midlayer7_maxgap=1 midlayer7_minwidth=1 midlayer7_maxwidth=1 midlayer7_prefwidth=1 midlayer12_mingap=5.85 midlayer12_prefgap=5.85 midlayer12_minwidth=3.15 midlayer12_maxwidth=3.15 midlayer12_prefwidth=3.15 bottomlayer_mingap=5.7 bottomlayer_maxgap=5.7 bottomlayer_prefgap=5.7 bottomlayer_minwidth=3.3 bottomlayer_maxwidth=3.3 bottomlayer_prefwidth=3.3 maxuncoupledlength=500
DiffPairsRouting DiffPairsRouting_90ohm [InDifferentialPairClass('DiffPair_90ohm')] p2: maxlimit=5.15 minlimit=1 mostfreqgap=1 toplayer_mingap=4.95 toplayer_maxgap=4.95 toplayer_prefgap=4.95 toplayer_minwidth=4.05 toplayer_maxwidth=4.05 toplayer_prefwidth=4.05 midlayer1_mingap=5.15 midlayer1_prefgap=5.15 midlayer1_minwidth=3.85 midlayer1_maxwidth=3.85 midlayer1_prefwidth=3.85 midlayer2_maxgap=1 midlayer2_minwidth=1 midlayer2_maxwidth=1 midlayer2_prefwidth=1 midlayer3_maxgap=1 midlayer3_minwidth=1 midlayer3_maxwidth=1 midlayer3_prefwidth=1 midlayer4_maxgap=1 midlayer4_minwidth=1 midlayer4_maxwidth=1 midlayer4_prefwidth=1 midlayer5_maxgap=1 midlayer5_minwidth=1 midlayer5_maxwidth=1 midlayer5_prefwidth=1 midlayer6_maxgap=1 midlayer6_minwidth=1 midlayer6_maxwidth=1 midlayer6_prefwidth=1 midlayer7_maxgap=1 midlayer7_minwidth=1 midlayer7_maxwidth=1 midlayer7_prefwidth=1 midlayer12_mingap=5.15 midlayer12_prefgap=5.15 midlayer12_minwidth=3.85 midlayer12_maxwidth=3.85 midlayer12_prefwidth=3.85 bottomlayer_mingap=4.95 bottomlayer_maxgap=4.95 bottomlayer_prefgap=4.95 bottomlayer_minwidth=4.05 bottomlayer_maxwidth=4.05 bottomlayer_prefwidth=4.05 maxuncoupledlength=500
DiffPairsRouting [All] p3: maxlimit=10 minlimit=10 mostfreqgap=10 toplayer_minwidth=15 toplayer_maxwidth=15 toplayer_prefwidth=15 midlayer1_minwidth=15 midlayer1_maxwidth=15 midlayer1_prefwidth=15 midlayer2_minwidth=15 midlayer2_maxwidth=15 midlayer2_prefwidth=15 midlayer3_minwidth=15 midlayer3_maxwidth=15 midlayer3_prefwidth=15 midlayer4_minwidth=15 midlayer4_maxwidth=15 midlayer4_prefwidth=15 midlayer5_minwidth=15 midlayer5_maxwidth=15 midlayer5_prefwidth=15 midlayer6_minwidth=15 midlayer6_maxwidth=15 midlayer6_prefwidth=15 midlayer7_minwidth=15 midlayer7_maxwidth=15 midlayer7_prefwidth=15 midlayer12_minwidth=15 midlayer12_maxwidth=15 midlayer12_prefwidth=15 bottomlayer_minwidth=15 bottomlayer_maxwidth=15 bottomlayer_prefwidth=15 maxuncoupledlength=500
HoleSize [All] p1: absolutevalues=TRUE maxlimit=250 minlimit=10 maxpercent=80.000 minpercent=20.000
HoleToHoleClearance TH-to-TH [IsThruVia vs IsThruVia] p1: gap=19.6 allowstackedmicrovias=TRUE
HoleToHoleClearance TH-to-buried [IsThruVia vs IsBuriedVia] p2: gap=23.5 allowstackedmicrovias=TRUE
HoleToHoleClearance TH-to-blind [IsThruVia vs IsBlindVia] p3: gap=13.7 allowstackedmicrovias=TRUE
HoleToHoleClearance Blind-to-blind [IsBlindVia vs IsBlindVia] p4: gap=11.8 allowstackedmicrovias=TRUE
MatchedLengths MatchedLengths_ETH_RGMII [InxSignalClass('xSignals_ETH_PHY_RGMII')] p1: tolerance=200 checknetsindiffpair=FALSE checkdiffpairvsdiffpair=TRUE checkxsignals=TRUE checkothers=TRUE
MatchedLengths MatchedLengths_ETH_TXRX [InxSignalClass('xSignals_ETH_PHY_TXRX')] p2: tolerance=100 checknetsindiffpair=FALSE checkdiffpairvsdiffpair=TRUE checkxsignals=TRUE checkothers=TRUE
MatchedLengths MatchedLengths_DiffPair_10mil [InxSignalClass('xSignals_ETH_PHY_RGMII') OR InxSignalClass('xSignals_ETH_PHY_TXRX') OR InxSignalClass('xSignals_QSFP1') OR InxSignalClass('xSignals_QSFP2') OR InxSignalClass('xSignals_SZG_PORTA') OR InxSignalClass('xSignals_SZG_PORTB') OR InxSignalClass('xSignals_SZG_PORTC') OR InxSignalClass('xSignals_SZG_PORTD') OR InxSignalClass('xSignals_SZG_PORTE') OR InxSignalClass('xSignals_SZG_PORTE_TXR') OR InxSignalClass('xSignals_SZG_PORTF') OR InxSignalClass('xSignals_SZG_PORTF_TXR') OR InxSignalClass('xSignals_USB-C_Connector_SS') OR InxSignalClass('xSignals_USB-C_SS') OR InxSignalClass('xSignals_SATA') OR InxSignalClass('xSignals_FPX1301') OR InxSignalClass('xSignals_DISPLAYPORT_PL_SNK') OR InxSignalClass('xSignals_DISPLAYPORT_PL_SRC') OR InxSignalClass('xSignals_DISPLAYPORT_PS_SRC')] p3: tolerance=10 checknetsindiffpair=TRUE checkdiffpairvsdiffpair=FALSE checkxsignals=FALSE checkothers=FALSE
MinimumSolderMaskSliver [All] p1: minsoldermaskwidth=3
PlaneClearance [All] p1: clearance=8
PlaneConnect GNDViaNoConnect [Name Like 'Free-ViaNoConnect*'] p1: planeconnectstyle=NoConnect reliefexpansion=20 reliefentries=4 reliefconductorwidth=10 reliefairgap=10
PlaneConnect [All] p2: planeconnectstyle=Relief reliefexpansion=20 reliefentries=4 reliefconductorwidth=10 reliefairgap=10
PolygonConnect [All] p1: connectstyle=Direct reliefconductorwidth=10 reliefentries=4 polygonreliefangle="90 Angle" airgapwidth=10
RoutingVias [All] p1: holewidth=28 width=50 viastyle="Through Hole" minholewidth=28 minwidth=50 maxholewidth=28 maxwidth=50
SilkToSilkClearance [All] p1: silktosilkclearance=0.1
SilkToSolderMaskClearance [IsPad] p1: minsilkscreentomaskgap=7.87 clearancetoexposedcopper=FALSE
SolderMaskExpansion [All] p1: expansion=2 istentingtop=FALSE
Width Width-50ohm [InNetClass('50ohm')] p1: maxlimit=4.55 minlimit=1 preferedwidth=1 toplayer_minwidth=4.55 toplayer_prefwidth=4.55 midlayer1_minwidth=4.05 midlayer1_maxwidth=4.05 midlayer1_prefwidth=4.05 midlayer2_maxwidth=1 midlayer3_maxwidth=1 midlayer4_maxwidth=1 midlayer5_maxwidth=1 midlayer6_maxwidth=1 midlayer7_maxwidth=1 midlayer12_minwidth=4.05 midlayer12_maxwidth=4.05 midlayer12_prefwidth=4.05 bottomlayer_minwidth=4.55 bottomlayer_prefwidth=4.55 minimp=50.000000 maximp=50.000000 favimp=50.000000
Width Width-Power [InNetClass('Power')] p2: maxlimit=100 minlimit=5 preferedwidth=10 midlayer1_minwidth=10 midlayer2_minwidth=10 midlayer3_minwidth=10 midlayer4_minwidth=10 midlayer5_minwidth=10 midlayer6_minwidth=10 midlayer7_minwidth=10 midlayer12_minwidth=10 minimp=50.000000 maximp=50.000000 favimp=50.000000
Width [All] p3: maxlimit=100 minlimit=4 preferedwidth=10 minimp=50.000000 maximp=50.000000 favimp=50.000000
22 further rules are at their usual default settings.

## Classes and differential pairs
net class SZG_PORTF: SZG_PORTF_C2P_CLKN SZG_PORTF_C2P_CLKP SZG_PORTF_P2C_CLKN SZG_PORTF_P2C_CLKP SZG_PORTF_REFCLKN SZG_PORTF_REFCLKP SZG_PORTF_RX0N SZG_PORTF_RX0P SZG_PORTF_RX1N SZG_PORTF_RX1P SZG_PORTF_RX2N SZG_PORTF_RX2P SZG_PORTF_RX3N SZG_PORTF_RX3P SZG_PORTF_S0 SZG_PORTF_S1 SZG_PORTF_S2 SZG_PORTF_S3 SZG_PORTF_S4 SZG_PORTF_S5 SZG_PORTF_S6 SZG_PORTF_S7 SZG_PORTF_S8 SZG_PORTF_S9 SZG_PORTF_TX0N SZG_PORTF_TX0P SZG_PORTF_TX1N SZG_PORTF_TX1P SZG_PORTF_TX2N SZG_PORTF_TX2P SZG_PORTF_TX3N SZG_PORTF_TX3P
net class SZG_PORTE: SZG_PORTE_C2P_CLKN SZG_PORTE_C2P_CLKP SZG_PORTE_P2C_CLKN SZG_PORTE_P2C_CLKP SZG_PORTE_REFCLKN SZG_PORTE_REFCLKP SZG_PORTE_RX0N SZG_PORTE_RX0P SZG_PORTE_RX1N SZG_PORTE_RX1P SZG_PORTE_RX2N SZG_PORTE_RX2P SZG_PORTE_RX3N SZG_PORTE_RX3P SZG_PORTE_S0 SZG_PORTE_S1 SZG_PORTE_S2 SZG_PORTE_S3 SZG_PORTE_S4 SZG_PORTE_S5 SZG_PORTE_S6 SZG_PORTE_S7 SZG_PORTE_S8 SZG_PORTE_S9 SZG_PORTE_TX0N SZG_PORTE_TX0P SZG_PORTE_TX1N SZG_PORTE_TX1P SZG_PORTE_TX2N SZG_PORTE_TX2P SZG_PORTE_TX3N SZG_PORTE_TX3P
net class SZG_PORTD: SZG_PORTD_C2P_CLKN SZG_PORTD_C2P_CLKP SZG_PORTD_P2C_CLKN SZG_PORTD_P2C_CLKP SZG_PORTD_S0_D0P SZG_PORTD_S1_D1P SZG_PORTD_S2_D0N SZG_PORTD_S3_D1N SZG_PORTD_S4_D2P SZG_PORTD_S5_D3P SZG_PORTD_S6_D2N SZG_PORTD_S7_D3N SZG_PORTD_S8_D4P SZG_PORTD_S9_D5P SZG_PORTD_S10_D4N SZG_PORTD_S11_D5N SZG_PORTD_S12_D6P SZG_PORTD_S13_D7P SZG_PORTD_S14_D6N SZG_PORTD_S15_D7N SZG_PORTD_S16 SZG_PORTD_S17 SZG_PORTD_S18 SZG_PORTD_S19 SZG_PORTD_S20 SZG_PORTD_S21 SZG_PORTD_S22 SZG_PORTD_S23 SZG_PORTD_S24 SZG_PORTD_S25 SZG_PORTD_S26 SZG_PORTD_S27
net class SZG_PORTC: SZG_PORTC_C2P_CLKN SZG_PORTC_C2P_CLKP SZG_PORTC_P2C_CLKN SZG_PORTC_P2C_CLKP SZG_PORTC_S0_D0P SZG_PORTC_S1_D1P SZG_PORTC_S2_D0N SZG_PORTC_S3_D1N SZG_PORTC_S4_D2P SZG_PORTC_S5_D3P SZG_PORTC_S6_D2N SZG_PORTC_S7_D3N SZG_PORTC_S8_D4P SZG_PORTC_S9_D5P SZG_PORTC_S10_D4N SZG_PORTC_S11_D5N SZG_PORTC_S12_D6P SZG_PORTC_S13_D7P SZG_PORTC_S14_D6N SZG_PORTC_S15_D7N SZG_PORTC_S16 SZG_PORTC_S17 SZG_PORTC_S18 SZG_PORTC_S19 SZG_PORTC_S20 SZG_PORTC_S21 SZG_PORTC_S22 SZG_PORTC_S23 SZG_PORTC_S24 SZG_PORTC_S25 SZG_PORTC_S26 SZG_PORTC_S27
net class SZG_PORTB: SZG_PORTB_C2P_CLKN SZG_PORTB_C2P_CLKP SZG_PORTB_P2C_CLKN SZG_PORTB_P2C_CLKP SZG_PORTB_S0_D0P SZG_PORTB_S1_D1P SZG_PORTB_S2_D0N SZG_PORTB_S3_D1N SZG_PORTB_S4_D2P SZG_PORTB_S5_D3P SZG_PORTB_S6_D2N SZG_PORTB_S7_D3N SZG_PORTB_S8_D4P SZG_PORTB_S9_D5P SZG_PORTB_S10_D4N SZG_PORTB_S11_D5N SZG_PORTB_S12_D6P SZG_PORTB_S13_D7P SZG_PORTB_S14_D6N SZG_PORTB_S15_D7N SZG_PORTB_S16 SZG_PORTB_S17 SZG_PORTB_S18 SZG_PORTB_S19 SZG_PORTB_S20 SZG_PORTB_S21 SZG_PORTB_S22 SZG_PORTB_S23 SZG_PORTB_S24 SZG_PORTB_S25 SZG_PORTB_S26 SZG_PORTB_S27
net class SZG_PORTA: SZG_PORTA_C2P_CLKN SZG_PORTA_C2P_CLKP SZG_PORTA_P2C_CLKN SZG_PORTA_P2C_CLKP SZG_PORTA_S0_D0P SZG_PORTA_S1_D1P SZG_PORTA_S2_D0N SZG_PORTA_S3_D1N SZG_PORTA_S4_D2P SZG_PORTA_S5_D3P SZG_PORTA_S6_D2N SZG_PORTA_S7_D3N SZG_PORTA_S8_D4P SZG_PORTA_S9_D5P SZG_PORTA_S10_D4N SZG_PORTA_S11_D5N SZG_PORTA_S12_D6P SZG_PORTA_S13_D7P SZG_PORTA_S14_D6N SZG_PORTA_S15_D7N SZG_PORTA_S16 SZG_PORTA_S17 SZG_PORTA_S18 SZG_PORTA_S19 SZG_PORTA_S20 SZG_PORTA_S21 SZG_PORTA_S22 SZG_PORTA_S23 SZG_PORTA_S24 SZG_PORTA_S25 SZG_PORTA_S26 SZG_PORTA_S27
differential pair class DiffPair_90ohm: DP_USB_D DP_USB_SSRX DP_USB_SSRX1 DP_USB_SSRX2 DP_USB_SSTX DP_USB_SSTX1 DP_USB_SSTX1_C DP_USB_SSTX2 DP_USB_SSTX2_C DP_USB_SSTX_C
net class PS_JTAG: PS_JTAG_TCK PS_JTAG_TDI PS_JTAG_TDO PS_JTAG_TMS
net class PS_Config: PS_DONE PS_ERROR_OUT PS_ERROR_STATUS PS_INIT_B PS_MODE0 PS_MODE1 PS_MODE2 PS_MODE3 PS_PROG_B PS_SRST_B
net class 50ohm: GIGE_MDC GIGE_MDIO GIGE_RESET_B GIGE_RX_CLK GIGE_RX_DV GIGE_RXD0 GIGE_RXD1 GIGE_RXD2 GIGE_RXD3 GIGE_TX_CLK GIGE_TX_EN GIGE_TXD0 GIGE_TXD1 GIGE_TXD2 GIGE_TXD3 PS_B500_MIO0 PS_B500_MIO1 PS_B500_MIO2 PS_B500_MIO4 PS_B500_MIO5 PS_B500_MIO7 PS_B500_MIO8 PS_B500_MIO11 PS_B500_MIO12 PS_B500_MIO13 PS_B500_MIO19 PS_B500_MIO20 PS_B500_MIO21 PS_B500_MIO22 PS_B500_MIO23 PS_B500_MIO24 PS_B500_MIO25 SZG_PORTA_S16 SZG_PORTA_S17 SZG_PORTA_S18 SZG_PORTA_S19 SZG_PORTA_S20 SZG_PORTA_S21 SZG_PORTA_S22 SZG_PORTA_S23 SZG_PORTA_S24 SZG_PORTA_S25 SZG_PORTA_S26 SZG_PORTA_S27 SZG_PORTB_S16 SZG_PORTB_S17 SZG_PORTB_S18 SZG_PORTB_S19 SZG_PORTB_S20 SZG_PORTB_S21 SZG_PORTB_S22 SZG_PORTB_S23 SZG_PORTB_S24 SZG_PORTB_S25 SZG_PORTB_S26 SZG_PORTB_S27 SZG_PORTC_S16 SZG_PORTC_S17 SZG_PORTC_S18 SZG_PORTC_S19 SZG_PORTC_S20 SZG_PORTC_S21 SZG_PORTC_S22 SZG_PORTC_S23 SZG_PORTC_S24 SZG_PORTC_S25 SZG_PORTC_S26 SZG_PORTC_S27 SZG_PORTD_S16 SZG_PORTD_S17 SZG_PORTD_S18 SZG_PORTD_S19 SZG_PORTD_S20 SZG_PORTD_S21 SZG_PORTD_S22 SZG_PORTD_S23 SZG_PORTD_S24 SZG_PORTD_S25 SZG_PORTD_S26 SZG_PORTD_S27 SZG_PORTE_S0 SZG_PORTE_S1 SZG_PORTE_S2 SZG_PORTE_S3 SZG_PORTE_S4 SZG_PORTE_S5 SZG_PORTE_S6 SZG_PORTE_S7 SZG_PORTE_S8 SZG_PORTE_S9 SZG_PORTF_S0 SZG_PORTF_S1 SZG_PORTF_S2 SZG_PORTF_S3 SZG_PORTF_S4 SZG_PORTF_S5 SZG_PORTF_S6 SZG_PORTF_S7 SZG_PORTF_S8 SZG_PORTF_S9 USB_CLKOUT USB_DATA0 USB_DATA1 USB_DATA2 USB_DATA3 USB_DATA4 USB_DATA5 USB_DATA6 USB_DATA7 USB_DIR USB_NXT USB_RESET_B USB_STP
differential pair class DiffPair_100ohm: DP_B68_L3 DP_B68_L13 DP_B68_L14 DP_B68_L15 DP_B68_L16 DP_CLK0 DP_CLK1 DP_CLK2 DP_CLK3 DP_DISPLAYPORT_PL_SNK_AUX DP_DISPLAYPORT_PL_SNK_AUX_C DP_DISPLAYPORT_PL_SNK_CONN_AUX DP_DISPLAYPORT_PL_SNK_CONN_AUX_C DP_DISPLAYPORT_PL_SNK_CONN_LANE0 DP_DISPLAYPORT_PL_SNK_CONN_LANE1 DP_DISPLAYPORT_PL_SNK_LANE0 DP_DISPLAYPORT_PL_SNK_LANE0_C DP_DISPLAYPORT_PL_SNK_LANE1 DP_DISPLAYPORT_PL_SNK_LANE1_C DP_DISPLAYPORT_PL_SRC_AUX DP_DISPLAYPORT_PL_SRC_AUX_C DP_DISPLAYPORT_PL_SRC_CONN_LANE0 DP_DISPLAYPORT_PL_SRC_CONN_LANE0_C DP_DISPLAYPORT_PL_SRC_CONN_LANE1 DP_DISPLAYPORT_PL_SRC_CONN_LANE1_C DP_DISPLAYPORT_PL_SRC_LANE0 DP_DISPLAYPORT_PL_SRC_LANE0_C DP_DISPLAYPORT_PL_SRC_LANE1 DP_DISPLAYPORT_PL_SRC_LANE1_N_C DP_DISPLAYPORT_PS_SRC_AUX DP_DISPLAYPORT_PS_SRC_AUX_C DP_DISPLAYPORT_PS_SRC_CONN_LANE0 DP_DISPLAYPORT_PS_SRC_CONN_LANE0_C DP_DISPLAYPORT_PS_SRC_CONN_LANE1 DP_DISPLAYPORT_PS_SRC_CONN_LANE1_C DP_DISPLAYPORT_PS_SRC_LANE0 DP_DISPLAYPORT_PS_SRC_LANE0_C DP_DISPLAYPORT_PS_SRC_LANE1 DP_DISPLAYPORT_PS_SRC_LANE1_C DP_ETH_TXRX_A DP_ETH_TXRX_A_ DP_ETH_TXRX_B DP_ETH_TXRX_B_ DP_ETH_TXRX_C DP_ETH_TXRX_C_ DP_ETH_TXRX_D DP_ETH_TXRX_D_ DP_FPX1301_RX0 DP_FPX1301_RX0_C DP_FPX1301_RX1 DP_FPX1301_RX1_C DP_FPX1301_TX0 DP_FPX1301_TX0_C DP_FPX1301_TX1 DP_FPX1301_TX1_C DP_PORTA_C2P_CLK DP_PORTA_D0 DP_PORTA_D1 DP_PORTA_D2 DP_PORTA_D3 DP_PORTA_D4 DP_PORTA_D5 DP_PORTA_D6 DP_PORTA_D7 DP_PORTA_P2C_CLK DP_PORTB_C2P_CLK DP_PORTB_D0 DP_PORTB_D1 DP_PORTB_D2 DP_PORTB_D3 DP_PORTB_D4 DP_PORTB_D5 DP_PORTB_D6 DP_PORTB_D7 DP_PORTB_P2C_CLK DP_PORTC_C2P_CLK DP_PORTC_D0 DP_PORTC_D1 DP_PORTC_D2 DP_PORTC_D3 DP_PORTC_D4 DP_PORTC_D5 DP_PORTC_D6 DP_PORTC_D7 DP_PORTC_P2C_CLK DP_PORTD_C2P_CLK DP_PORTD_D0 DP_PORTD_D1 DP_PORTD_D2 DP_PORTD_D3 DP_PORTD_D4 DP_PORTD_D5 DP_PORTD_D6 DP_PORTD_D7 DP_PORTD_P2C_CLK DP_PORTE_C2P DP_PORTE_P2C_CLK DP_PORTE_REFCLK DP_PORTE_RX0 DP_PORTE_RX1 DP_PORTE_RX2 DP_PORTE_RX3 DP_PORTE_TX0 DP_PORTE_TX1 DP_PORTE_TX2 DP_PORTE_TX3 DP_PORTF_C2P_CLK DP_PORTF_P2C_CLK DP_PORTF_REFCLK DP_PORTF_RX0 DP_PORTF_RX1 DP_PORTF_RX2 DP_PORTF_RX3 DP_PORTF_TX0 DP_PORTF_TX1 DP_PORTF_TX2 DP_PORTF_TX3 DP_QSFP1_RX1 DP_QSFP1_RX2 DP_QSFP1_RX3 DP_QSFP1_RX4 DP_QSFP1_TX1 DP_QSFP1_TX2 DP_QSFP1_TX3 DP_QSFP1_TX4 DP_QSFP2_RX1 DP_QSFP2_RX2 DP_QSFP2_RX3 DP_QSFP2_RX4 DP_QSFP2_TX1 DP_QSFP2_TX2 DP_QSFP2_TX3 DP_QSFP2_TX4 DP_SATA_TXA DP_SATA_TXA_C DP_SATA_TXB DP_SATA_TXB_C DP_XADC_V
net class Power: +1.2V_DP +1.2V_ETH +1.8V +1.8V_AUX +3.3V +3.3V_AUX +3.3V_QSFP +3.3V_QSFP_VCC1 +3.3V_QSFP_VCCRX2 +3.3V_QSFP_VCCTX1 +5V_AUX +5V_SZG +VDCIN AVDDH_KSZ9031 AVDDL_KSZ9031 AVDDL_PLL_KSZ9031 DGND USB_VBUS VCC_EEPROM_FPX1301 VCCO_28 VCCO_67 VCCO_68 VCCO_87_88 VDDD VREF_28 VREF_67 VREF_68
differential pair DP_USB_SSTX2_C: +USB_SSTXP2_R -USB_SSTXN2_C
differential pair DP_USB_SSTX1_C: +USB_SSTXP1_C -USB_SSTXN1_C
differential pair DP_DISPLAYPORT_PS_SRC_AUX_C: +DISPLAYPORT_PS_SRC_AUX_P_C -DISPLAYPORT_PS_SRC_AUX_N_C
differential pair DP_DISPLAYPORT_PL_SRC_AUX_C: +DISPLAYPORT_PL_SRC_AUX_P_C -DISPLAYPORT_PL_SRC_AUX_N_C
differential pair DP_B68_L14: +B68_L14P_N2 -B68_L14N_N3
differential pair DP_B68_L15: +B68_L15P_N4 -B68_L15N_N5
differential pair DP_B68_L16: +B68_L16P_N6 -B68_L16N_N7
differential pair DP_B68_L13: +B68_L13P_N0 -B68_L13N_N1
differential pair DP_B68_L3: +B68_L3P_N4 -B68_L3N_N5
differential pair DP_CLK3: +CLK3A -CLK3B
differential pair DP_QSFP2_TX4: +QSFP2_TX4P -QSFP2_TX4N
differential pair DP_SATA_TXB_C: +SATA_TXB+_C -SATA_TXB-_C
differential pair DP_SATA_TXB: +SATA_TXB+ -SATA_TXB-
differential pair DP_SATA_TXA_C: +SATA_TXA+_C -SATA_TXA-_C
differential pair DP_SATA_TXA: +SATA_TXA+ -SATA_TXA-
differential pair DP_QSFP2_TX3: +QSFP2_TX3P -QSFP2_TX3N
differential pair DP_QSFP2_TX2: +QSFP2_TX2P -QSFP2_TX2N
differential pair DP_QSFP2_TX1: +QSFP2_TX1P -QSFP2_TX1N
differential pair DP_QSFP2_RX4: +QSFP2_RX4P -QSFP2_RX4N
differential pair DP_QSFP2_RX3: +QSFP2_RX3P -QSFP2_RX3N
differential pair DP_QSFP2_RX2: +QSFP2_RX2P -QSFP2_RX2N
differential pair DP_QSFP2_RX1: +QSFP2_RX1P -QSFP2_RX1N
differential pair DP_QSFP1_TX4: +QSFP1_TX4P -QSFP1_TX4N
differential pair DP_QSFP1_TX3: +QSFP1_TX3P -QSFP1_TX3N
differential pair DP_QSFP1_TX2: +QSFP1_TX2P -QSFP1_TX2N
differential pair DP_QSFP1_RX4: +QSFP1_RX4P -QSFP1_RX4N
differential pair DP_QSFP1_RX3: +QSFP1_RX3P -QSFP1_RX3N
differential pair DP_QSFP1_RX2: +QSFP1_RX2P -QSFP1_RX2N
differential pair DP_QSFP1_TX1: +QSFP1_TX1P -QSFP1_TX1N
differential pair DP_QSFP1_RX1: +QSFP1_RX1P -QSFP1_RX1N
differential pair DP_PORTF_TX3: +SZG_PORTF_TX3P -SZG_PORTF_TX3N
differential pair DP_PORTF_TX2: +SZG_PORTF_TX2P -SZG_PORTF_TX2N
differential pair DP_PORTF_TX1: +SZG_PORTF_TX1P -SZG_PORTF_TX1N
differential pair DP_PORTF_TX0: +SZG_PORTF_TX0P -SZG_PORTF_TX0N
differential pair DP_PORTF_RX3: +SZG_PORTF_RX3P -SZG_PORTF_RX3N
differential pair DP_PORTF_RX2: +SZG_PORTF_RX2P -SZG_PORTF_RX2N
differential pair DP_PORTF_RX1: +SZG_PORTF_RX1P -SZG_PORTF_RX1N
differential pair DP_PORTF_RX0: +SZG_PORTF_RX0P -SZG_PORTF_RX0N
differential pair DP_PORTE_TX3: +SZG_PORTE_TX3P -SZG_PORTE_TX3N
differential pair DP_PORTF_REFCLK: +SZG_PORTF_REFCLKP -SZG_PORTF_REFCLKN
differential pair DP_PORTF_P2C_CLK: +SZG_PORTF_P2C_CLKP -SZG_PORTF_P2C_CLKN
differential pair DP_PORTF_C2P_CLK: +SZG_PORTF_C2P_CLKP -SZG_PORTF_C2P_CLKN
differential pair DP_PORTE_TX2: +SZG_PORTE_TX2P -SZG_PORTE_TX2N
differential pair DP_PORTE_TX1: +SZG_PORTE_TX1P -SZG_PORTE_TX1N
differential pair DP_PORTE_TX0: +SZG_PORTE_TX0P -SZG_PORTE_TX0N
differential pair DP_PORTE_RX3: +SZG_PORTE_RX3P -SZG_PORTE_RX3N
differential pair DP_PORTE_RX2: +SZG_PORTE_RX2P -SZG_PORTE_RX2N
differential pair DP_PORTE_RX1: +SZG_PORTE_RX1P -SZG_PORTE_RX1N
differential pair DP_PORTE_RX0: +SZG_PORTE_RX0P -SZG_PORTE_RX0N
differential pair DP_PORTE_REFCLK: +SZG_PORTE_REFCLKP -SZG_PORTE_REFCLKN
differential pair DP_PORTE_P2C_CLK: +SZG_PORTE_P2C_CLKP -SZG_PORTE_P2C_CLKN
differential pair DP_PORTE_C2P: +SZG_PORTE_C2P_CLKP -SZG_PORTE_C2P_CLKN
differential pair DP_PORTD_D7: +SZG_PORTD_S13_D7P -SZG_PORTD_S15_D7N
differential pair DP_PORTD_D6: +SZG_PORTD_S12_D6P -SZG_PORTD_S14_D6N
differential pair DP_PORTD_D5: +SZG_PORTD_S9_D5P -SZG_PORTD_S11_D5N
differential pair DP_PORTD_D4: +SZG_PORTD_S8_D4P -SZG_PORTD_S10_D4N
differential pair DP_PORTD_D3: +SZG_PORTD_S5_D3P -SZG_PORTD_S7_D3N
differential pair DP_PORTD_D2: +SZG_PORTD_S4_D2P -SZG_PORTD_S6_D2N
differential pair DP_PORTD_D1: +SZG_PORTD_S1_D1P -SZG_PORTD_S3_D1N
differential pair DP_PORTD_D0: +SZG_PORTD_S0_D0P -SZG_PORTD_S2_D0N
differential pair DP_PORTD_P2C_CLK: +SZG_PORTD_P2C_CLKP -SZG_PORTD_P2C_CLKN
differential pair DP_PORTD_C2P_CLK: +SZG_PORTD_C2P_CLKP -SZG_PORTD_C2P_CLKN
differential pair DP_PORTC_D7: +SZG_PORTC_S13_D7P -SZG_PORTC_S15_D7N
differential pair DP_PORTC_D6: +SZG_PORTC_S12_D6P -SZG_PORTC_S14_D6N
differential pair DP_PORTC_D5: +SZG_PORTC_S9_D5P -SZG_PORTC_S11_D5N
differential pair DP_PORTC_D4: +SZG_PORTC_S8_D4P -SZG_PORTC_S10_D4N
differential pair DP_PORTC_D3: +SZG_PORTC_S5_D3P -SZG_PORTC_S7_D3N
differential pair DP_PORTC_D2: +SZG_PORTC_S4_D2P -SZG_PORTC_S6_D2N
differential pair DP_PORTC_D1: +SZG_PORTC_S1_D1P -SZG_PORTC_S3_D1N
differential pair DP_PORTC_D0: +SZG_PORTC_S0_D0P -SZG_PORTC_S2_D0N
differential pair DP_PORTC_P2C_CLK: +SZG_PORTC_P2C_CLKP -SZG_PORTC_P2C_CLKN
differential pair DP_PORTC_C2P_CLK: +SZG_PORTC_C2P_CLKP -SZG_PORTC_C2P_CLKN
differential pair DP_PORTB_D7: +SZG_PORTB_S13_D7P -SZG_PORTB_S15_D7N
differential pair DP_PORTB_D6: +SZG_PORTB_S12_D6P -SZG_PORTB_S14_D6N
differential pair DP_PORTB_D5: +SZG_PORTB_S9_D5P -SZG_PORTB_S11_D5N
differential pair DP_PORTB_D4: +SZG_PORTB_S8_D4P -SZG_PORTB_S10_D4N
differential pair DP_PORTB_D3: +SZG_PORTB_S5_D3P -SZG_PORTB_S7_D3N
differential pair DP_PORTB_D2: +SZG_PORTB_S4_D2P -SZG_PORTB_S6_D2N
differential pair DP_PORTB_D1: +SZG_PORTB_S1_D1P -SZG_PORTB_S3_D1N
differential pair DP_PORTB_D0: +SZG_PORTB_S0_D0P -SZG_PORTB_S2_D0N
differential pair DP_PORTB_P2C_CLK: +SZG_PORTB_P2C_CLKP -SZG_PORTB_P2C_CLKN
differential pair DP_PORTB_C2P_CLK: +SZG_PORTB_C2P_CLKP -SZG_PORTB_C2P_CLKN
differential pair DP_PORTA_D7: +SZG_PORTA_S13_D7P -SZG_PORTA_S15_D7N
differential pair DP_PORTA_D6: +SZG_PORTA_S12_D6P -SZG_PORTA_S14_D6N
differential pair DP_ETH_TXRX_A_: +ETH_TXRX_A_P -ETH_TXRX_A_N
differential pair DP_ETH_TXRX_B_: +ETH_TXRX_B_P -ETH_TXRX_B_N
differential pair DP_ETH_TXRX_C_: +ETH_TXRX_C_P -ETH_TXRX_C_N
differential pair DP_ETH_TXRX_D_: +ETH_TXRX_D_P -ETH_TXRX_D_N
differential pair DP_USB_D: +USB_DP -USB_DN
differential pair DP_XADC_V: +XADC_VP -XADC_VN
differential pair DP_PORTA_D5: +SZG_PORTA_S9_D5P -SZG_PORTA_S11_D5N
differential pair DP_PORTA_D4: +SZG_PORTA_S8_D4P -SZG_PORTA_S10_D4N
differential pair DP_PORTA_D3: +SZG_PORTA_S5_D3P -SZG_PORTA_S7_D3N
differential pair DP_PORTA_D2: +SZG_PORTA_S4_D2P -SZG_PORTA_S6_D2N
differential pair DP_PORTA_D1: +SZG_PORTA_S1_D1P -SZG_PORTA_S3_D1N
differential pair DP_PORTA_D0: +SZG_PORTA_S0_D0P -SZG_PORTA_S2_D0N
differential pair DP_PORTA_P2C_CLK: +SZG_PORTA_P2C_CLKP -SZG_PORTA_P2C_CLKN
differential pair DP_PORTA_C2P_CLK: +SZG_PORTA_C2P_CLKP -SZG_PORTA_C2P_CLKN
differential pair DP_FPX1301_TX1_C: +FPX1301_TXP1_C -FPX1301_TXN1_C
differential pair DP_FPX1301_TX1: +FPX1301_TXP1 -FPX1301_TXN1
differential pair DP_FPX1301_TX0_C: +FPX1301_TXP0_C -FPX1301_TXN0_C
differential pair DP_FPX1301_TX0: +FPX1301_TXP0 -FPX1301_TXN0
differential pair DP_FPX1301_RX1_C: +FPX1301_RXP1_C -FPX1301_RXN1_C
differential pair DP_FPX1301_RX1: +FPX1301_RXP1 -FPX1301_RXN1
differential pair DP_FPX1301_RX0_C: +FPX1301_RXP0_C -FPX1301_RXN0_C
differential pair DP_FPX1301_RX0: +FPX1301_RXP0 -FPX1301_RXN0
differential pair DP_DISPLAYPORT_PS_SRC_LANE1_C: +"" -""
differential pair DP_DISPLAYPORT_PS_SRC_LANE1: +DISPLAYPORT_PS_SRC_LANE1_P -DISPLAYPORT_PS_SRC_LANE1_N
differential pair DP_DISPLAYPORT_PS_SRC_LANE0_C: +"" -""
differential pair DP_DISPLAYPORT_PS_SRC_LANE0: +DISPLAYPORT_PS_SRC_LANE0_P -DISPLAYPORT_PS_SRC_LANE0_N
differential pair DP_DISPLAYPORT_PS_SRC_CONN_LANE1_C: +"" -""
differential pair DP_DISPLAYPORT_PS_SRC_CONN_LANE1: +DISPLAYPORT_PS_SRC_CONN_LANE1_P -DISPLAYPORT_PS_SRC_CONN_LANE1_N
differential pair DP_DISPLAYPORT_PS_SRC_CONN_LANE0_C: +"" -""
differential pair DP_DISPLAYPORT_PS_SRC_CONN_LANE0: +DISPLAYPORT_PS_SRC_CONN_LANE0_P -DISPLAYPORT_PS_SRC_CONN_LANE0_N
differential pair DP_DISPLAYPORT_PS_SRC_AUX: +DISPLAYPORT_PS_SRC_AUX_P -DISPLAYPORT_PS_SRC_AUX_N
differential pair DP_DISPLAYPORT_PL_SRC_LANE1_N_C: +DISPLAYPORT_PL_SRC_LANE1_P_C -DISPLAYPORT_PL_SRC_LANE1_N_C
differential pair DP_DISPLAYPORT_PL_SRC_LANE1: +DISPLAYPORT_PL_SRC_LANE1_P -DISPLAYPORT_PL_SRC_LANE1_N
differential pair DP_DISPLAYPORT_PL_SRC_LANE0_C: +DISPLAYPORT_PL_SRC_LANE0_P_C -DISPLAYPORT_PL_SRC_LANE0_N_C
differential pair DP_DISPLAYPORT_PL_SRC_LANE0: +DISPLAYPORT_PL_SRC_LANE0_P -DISPLAYPORT_PL_SRC_LANE0_N
differential pair DP_DISPLAYPORT_PL_SRC_CONN_LANE1_C: +DISPLAYPORT_PL_SRC_CONN_LANE1_P_C -DISPLAYPORT_PL_SRC_CONN_LANE1_N_C
differential pair DP_DISPLAYPORT_PL_SRC_CONN_LANE1: +DISPLAYPORT_PL_SRC_CONN_LANE1_P -DISPLAYPORT_PL_SRC_CONN_LANE1_N
differential pair DP_DISPLAYPORT_PL_SRC_CONN_LANE0_C: +DISPLAYPORT_PL_SRC_CONN_LANE0_P_C -DISPLAYPORT_PL_SRC_CONN_LANE0_N_C
differential pair DP_DISPLAYPORT_PL_SRC_CONN_LANE0: +DISPLAYPORT_PL_SRC_CONN_LANE0_P -DISPLAYPORT_PL_SRC_CONN_LANE0_N
differential pair DP_DISPLAYPORT_PL_SRC_AUX: +DISPLAYPORT_PL_SRC_AUX_P -DISPLAYPORT_PL_SRC_AUX_N
differential pair DP_DISPLAYPORT_PL_SNK_LANE1_C: +DISPLAYPORT_PL_SNK_LANE1_P_C -DISPLAYPORT_PL_SNK_LANE1_N_C
differential pair DP_DISPLAYPORT_PL_SNK_LANE1: +DISPLAYPORT_PL_SNK_LANE1_P -DISPLAYPORT_PL_SNK_LANE1_N
differential pair DP_DISPLAYPORT_PL_SNK_LANE0_C: +DISPLAYPORT_PL_SNK_LANE0_P_C -DISPLAYPORT_PL_SNK_LANE0_N_C
differential pair DP_DISPLAYPORT_PL_SNK_LANE0: +DISPLAYPORT_PL_SNK_LANE0_P -DISPLAYPORT_PL_SNK_LANE0_N
differential pair DP_DISPLAYPORT_PL_SNK_CONN_LANE1: +DISPLAYPORT_PL_SNK_CONN_LANE1_P -DISPLAYPORT_PL_SNK_CONN_LANE1_N
differential pair DP_DISPLAYPORT_PL_SNK_CONN_LANE0: +DISPLAYPORT_PL_SNK_CONN_LANE0_P -DISPLAYPORT_PL_SNK_CONN_LANE0_N
differential pair DP_DISPLAYPORT_PL_SNK_CONN_AUX_C: +DISPLAYPORT_PL_SNK_CONN_AUX_P_C -DISPLAYPORT_PL_SNK_CONN_AUX_N_C
differential pair DP_DISPLAYPORT_PL_SNK_CONN_AUX: +DISPLAYPORT_PL_SNK_CONN_AUX_P -DISPLAYPORT_PL_SNK_CONN_AUX_N
differential pair DP_DISPLAYPORT_PL_SNK_AUX_C: +DISPLAYPORT_PL_SNK_AUX_P_C -DISPLAYPORT_PL_SNK_AUX_N_C
differential pair DP_DISPLAYPORT_PL_SNK_AUX: +DISPLAYPORT_PL_SNK_AUX_P -DISPLAYPORT_PL_SNK_AUX_N
differential pair DP_CLK2: +CLK2A -CLK2B
differential pair DP_CLK1: +CLK1A -CLK1B
differential pair DP_CLK0: +CLK0A -CLK0B
differential pair DP_ETH_TXRX_A: +ETH_TXRX_A_P -ETH_TXRX_A_N
differential pair DP_ETH_TXRX_B: +ETH_TXRX_B_P -ETH_TXRX_B_N
differential pair DP_ETH_TXRX_C: +ETH_TXRX_C_P -ETH_TXRX_C_N
differential pair DP_ETH_TXRX_D: +ETH_TXRX_D_P -ETH_TXRX_D_N
differential pair DP_USB_SSTX2: +USB_SSTXP2 -USB_SSTXN2
differential pair DP_USB_SSTX1: +USB_SSTXP1 -USB_SSTXN1
differential pair DP_USB_SSTX_C: +"" -""
differential pair DP_USB_SSTX: +USB_SSTX_P -USB_SSTX_N
differential pair DP_USB_SSRX2: +USB_SSRXP2 -USB_SSRXN2
differential pair DP_USB_SSRX1: +USB_SSRXP1 -USB_SSRXN1
differential pair DP_USB_SSRX: +USB_SSRX_P -USB_SSRX_N

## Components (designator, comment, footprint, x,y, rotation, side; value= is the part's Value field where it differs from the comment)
*1 "Opal Kelly Logo" okLogo-23x5 4880,996 r0 top
C1 "C0402C104K8PACTU" CAPC1005X06A#1 8602,5440 r270 top value="0.1 u"
C2 "C0402C104K8PACTU" CAPC1005X06A#2 7693,4930 r270 top value="0.1 u"
C3 "C0402C104K8PACTU" CAPC1005X06A#1 4436.23,873.79 r180 top value="0.1 u"
C4 "C0402C104K8PACTU" CAPC1005X06A#1 4156.23,953.79 r0 top value="0.1 u"
C5 "C0402C104K8PACTU" CAPC1005X06A#1 4436.23,953.79 r180 top value="0.1 u"
C6 "C0402C104K8PACTU" CAPC1005X06A#1 4279.23,1063.79 r270 top value="0.1 u"
C7 "C0402C104K8PACTU" CAPC1005X06A#1 4156.23,863.79 r0 top value="0.1 u"
C8 "C0402C104K8PACTU" CAPC1005X06A#1 4315.23,1063.79 r270 top value="0.1 u"
C9 "C0402C104K8PACTU" CAPC1005X06A#2 6459.6,1476.15 r270 top value="0.1 u"
C10 "C0402C104K8PACTU" CAPC1005X06A#2 6902,1707.01 r0 top value="0.1 u"
C11 "C0402C104K8PACTU" CAPC1005X06A#2 6902,1744.01 r0 top value="0.1 u"
C12 "C0402C104K8PACTU" CAPC1005X06A#2 6902,1812.5 r0 top value="0.1 u"
C13 "C0402C104K8PACTU" CAPC1005X06A#2 6902,1849.5 r0 top value="0.1 u"
C14 "C0402C104K8PACTU" CAPC1005X06A#2 6902,1918 r0 top value="0.1 u"
C15 "C0402C104K8PACTU" CAPC1005X06A#2 6902,1955 r0 top value="0.1 u"
C16 "C0402C104K8PACTU" CAPC1005X06A#2 6902,1992 r0 top value="0.1 u"
C17 "C0402C104K8PACTU" CAPC1005X06A#2 6902,2029 r0 top value="0.1 u"
C18 "C0402C104K8PACTU" CAPC1005X06A#1 1851,3073 r270 top value="0.1 u"
C19 "C0402C104K8PACTU" CAPC1005X06A#1 1901,3073 r270 top value="0.1 u"
C20 "TMK105BJ104KV-F" CAPC1005X06A#1 2380,3958 r180 top value="0.1 u"
C21 "TMK105BJ104KV-F" CAPC1005X06A#1 2822.08,3957 r0 top value="0.1 u"
C22 "C0402C104K8PACTU" CAPC1005X06A#1 3234.17,3320.17 r0 top value="0.1 u"
C23 "C0402C104K8PACTU" CAPC1005X06A#1 3234.38,3369.62 r0 top value="0.1 u"
C24 "SM-0402, 10%, 10v" CAPC1005X06A#1 926,364.08 r90 top value="0.1 u"
C25 "SM-0402, 10%, 10v" CAPC1005X06A#1 890,364 r90 top value="0.1 u"
C26 "SM-0402, 10%, 10v" CAPC1005X06A#1 775.15,364 r90 top value="0.1 u"
C27 "SM-0402, 10%, 10v" CAPC1005X06A#1 739.15,364 r90 top value="0.1 u"
C28 "SM-0402, 10%, 10v" CAPC1005X06A#1 7766.77,871.26 r270 top value="0.1 u"
C29 "SM-0402, 10%, 10v" CAPC1005X06A#1 7714.53,621 r0 top value="0.1 u"
C30 "SM-0402, 10%, 10v" CAPC1005X06A#1 7802.77,871.26 r270 top value="0.1 u"
C31 "SM-0402, 10%, 10v" CAPC1005X06A#1 7839.77,871.26 r270 top value="0.1 u"
C32 "SM-0402, 10%, 10v" CAPC1005X06A#1 7875.77,871.26 r270 top value="0.1 u"
C33 "SM-0402, 10%, 10v" CAPC1005X06A#1 7531,1217 r180 top value="0.1 u"
C34 "SM-0402, 10%, 10v" CAPC1005X06A#1 7531,1181 r180 top value="0.1 u"
C35 "SM-0402, 10%, 10v" CAPC1005X06A#1 7689.77,941.26 r0 top value="0.1 u"
C36 "SM-0402, 10%, 10v" CAPC1005X06A#1 7689.77,977.26 r0 top value="0.1 u"
C37 "C0402C103K4RACTU" CAPC1005X06A#1 8354,422 r180 top value="0.01 u"
C38 "CBR04C100J5GAC" CAPC1005X06A#1 8121.77,1063.34 r90 top value=10p
C39 "CBR04C100J5GAC" CAPC1005X06A#1 8121.77,1139.18 r270 top value=10p
C40 "C0402C104K8PACTU" CAPC1005X06A#1 7882.77,949.26 r90 top value="0.1 u"
C41 "C0402C104K8PACTU" CAPC1005X06A#1 7832.77,949.26 r90 top value="0.1 u"
C42 "C0402C104K8PACTU" CAPC1005X06A#1 7928.77,949.26 r90 top value="0.1 u"
C43 "C0402C104K8PACTU" CAPC1005X06A#1 7705.77,1160.26 r0 top value="0.1 u"
C44 "C0402C104K8PACTU" CAPC1005X06A#1 7991.77,1238.34 r270 top value="0.1 u"
C45 "C0402C104K8PACTU" CAPC1005X06A#1 8052.77,1180.26 r270 top value="0.1 u"
C46 "C0402C104K8PACTU" CAPC1005X06A#1 7761.77,1217.26 r0 top value="0.1 u"
C47 "C0402C104K8PACTU" CAPC1005X06A#1 7704.77,1088.26 r0 top value="0.1 u"
C48 "C0402C104K8PACTU" CAPC1005X06A#1 7704.77,1052.26 r0 top value="0.1 u"
C49 "SM-0402, 10%, 10v" CAPC1005X06A#1 6815.8,4219.72 r270 top value="0.1 u"
C50 "CL21A226MQQNNNE" CAPC2012X14N 6759.8,4219.72 r270 top value="22 u"
C51 "SM-0402, 10%, 10v" CAPC1005X06A#1 6818.01,4373.65 r270 top value="0.1 u"
C52 "CL21A226MQQNNNE" CAPC2012X14N 6762.01,4371.65 r270 top value="22 u"
C53 "C0402C104K8PACTU" CAPC1005X06A#1 6815.8,4083.72 r90 top value="0.1 u"
C54 "CL21A226MQQNNNE" CAPC2012X14N 6759.8,4084.72 r90 top value="22 u"
C55 "SM-0402, 10%, 10v" CAPC1005X06A#1 5484,3219 r0 top value="0.1 u"
C56 "SM-0402, 10%, 10v" CAPC1005X06A#1 5678.63,3227.66 r90 top value="0.1 u"
C57 "SM-0402, 10%, 10v" CAPC1005X06A#1 5508.46,3460.65 r0 top value="0.1 u"
C58 "SM-0402, 10%, 10v" CAPC1005X06A#1 5587.46,3519.65 r270 top value="0.1 u"
C59 "SM-0402, 10%, 10v" CAPC1005X06A#1 5509.46,3644.65 r0 top value="0.1 u"
C60 "SM-0402, 10%, 10v" CAPC1005X06A#1 5588.46,3703.65 r270 top value="0.1 u"
C61 "SM-0402, 10%, 10v" CAPC1005X06A#1 6815.79,3003.24 r270 top value="0.1 u"
C62 "CL21A226MQQNNNE" CAPC2012X14N 6759.79,3003.24 r270 top value="22 u"
C63 "SM-0402, 10%, 10v" CAPC1005X06A#1 6818,3157.18 r270 top value="0.1 u"
C64 "CL21A226MQQNNNE" CAPC2012X14N 6762,3155.18 r270 top value="22 u"
C65 "C0402C104K8PACTU" CAPC1005X06A#1 6815.79,2867.24 r90 top value="0.1 u"
C66 "CL21A226MQQNNNE" CAPC2012X14N 6759.79,2868.24 r90 top value="22 u"
C67 "SM-0402, 10%, 10v" CAPC1005X06A#1 5509.46,3011.65 r0 top value="0.1 u"
C68 "SM-0402, 10%, 10v" CAPC1005X06A#1 5588.46,3070.65 r270 top value="0.1 u"
C69 "JMK325ABJ227MM-T" CAPC3225N 5671.06,5441.96 r0 top value="220 u"
C70 "C0402C104K8PACTU" CAPC1005X06A#1 5777.06,5290.96 r90 top value="0.1 u"
C71 "C0402C104K8PACTU" CAPC1005X06A#1 5018.41,4631.87 r0 top value="0.1 u"
C72 "C0402C104K8PACTU" CAPC1005X06A#1 5018.41,4590.87 r0 top value="0.1 u"
C73 "JMK105BJ225MV-F" CAPC1005X06A#1 5186.41,4785.87 r270 top value="2.2 u"
C74 "C0402C104K8PACTU" CAPC1005X06A#1 5018.41,4549.87 r0 top value="0.1 u"
C75 "C0402C104K8PACTU" CAPC1005X06A#1 6161.35,5180 r90 top value="0.1 u"
C76 "C0402C104K8PACTU" CAPC1005X06A#1 5967.41,5288.32 r270 top value="0.1 u"
C77 "C0402C120J5GACTU" CAPC1005X06A#1 5000.41,4694.87 r270 top value="12 p"
C78 "C0402C120J5GACTU" CAPC1005X06A#1 5000.41,4769.87 r270 top value="12 p"
C79 "C0402C104K8PACTU" CAPC1005X06A#1 6158,5435 r90 top value="0.1 u"
C80 "C0402C104K8PACTU" CAPC1005X06A#1 6194,5435 r90 top value="0.1 u"
C81 "C0402C104K8PACTU" CAPC1005X06A#1 5824,5596 r0 top value="0.1 u"
C82 "C0402C104K8PACTU" CAPC1005X06A#2 4453.14,4977.14 r180 top value="0.1 u"
C83 "C0402C104K8PACTU" CAPC1005X06A#2 4350.06,4894.14 r90 top value="0.1 u"
C84 "C0402C104K8PACTU" CAPC1005X06A#2 4455.14,5196.14 r180 top value="0.1 u"
C85 "JMK105BBJ475MV-F" CAPC1005X06A#2 4451.61,4914.29 r90 top value=4.7u
C86 "JMK105BBJ475MV-F" CAPC1005X06A#2 4537.61,4914.29 r90 top value=4.7u
C87 "JMK105BBJ475MV-F" CAPC1005X06A#2 4092,5293 r90 top value=4.7u
C88 "C0402C104K8PACTU" CAPC1005X06A#2 4173.06,5276.14 r270 top value="0.1 u"
C89 "C0402C104K8PACTU" CAPC1005X06A#2 4351.06,5277.22 r270 top value="0.1 u"
C90 "C0402C104K8PACTU" CAPC1005X06A#2 4272.06,5276.14 r270 top value="0.1 u"
C91 "C0402C104K8PACTU" CAPC1005X06A#2 4069.06,5092.14 r0 top value="0.1 u"
C92 "C0402C104K8PACTU" CAPC1005X06A#2 4185.06,4891.14 r90 top value="0.1 u"
C93 "C0402C104K8PACTU" CAPC1005X06A#2 4068.06,5184.14 r0 top value="0.1 u"
C94 "C0402C104K8PACTU" CAPC1005X06A#1 7693,5178 r270 top value="0.1 u"
C95 "JMK105BBJ475MV-F" CAPC1005X06A#2 4552,4799.57 r270 top value=4.7u
C96 "JMK105BBJ475MV-F" CAPC1005X06A#2 4431,4803.57 r270 top value=4.7u
C97 "C0402C104K8PACTU" CAPC1005X06A#2 4291.06,4894.14 r90 top value="0.1 u"
C98 "C0402C104K8PACTU" CAPC1005X06A#2 4311.06,5276.14 r270 top value="0.1 u"
C99 "C0402C104K8PACTU" CAPC1005X06A#2 4068.06,5001.14 r0 top value="0.1 u"
C100 "C0402C104K8PACTU" CAPC1005X06A#2 4225.06,4891.14 r90 top value="0.1 u"
C101 "JMK105BBJ475MV-F" CAPC1005X06A#2 4530,5218 r90 top value=4.7u
C102 "JMK105BBJ475MV-F" CAPC1005X06A#2 4671.02,5072.07 r270 top value=4.7u
C103 "JMK105BBJ475MV-F" CAPC1005X06A#2 4550.02,5076.07 r270 top value=4.7u
C104 "C0402C104K8PACTU" CAPC1005X06A#2 4454.14,5035.14 r180 top value="0.1 u"
C105 "C0402C104K8PACTU" CAPC1005X06A#2 4452.14,5133.14 r180 top value="0.1 u"
C106 "C0402C104K8PACTU" CAPC1005X06A#1 5363,4951 r90 top value="0.1 u"
C107 "C0402C104K8PACTU" CAPC1005X06A#1 5326,4951 r90 top value="0.1 u"
C108 "C0402C104K8PACTU" CAPC1005X06A#1 5010,4951 r90 top value="0.1 u"
C109 "C0402C104K8PACTU" CAPC1005X06A#1 4973,4951 r90 top value="0.1 u"
C110 "C0402C180J5GACTU" CAPC1005X06A#2 4283.06,4797.14 r180 top value="18 p"
C111 "C0402C180J5GACTU" CAPC1005X06A#2 4358.06,4797.14 r0 top value="18 p"
C112 "LMK212BJ106KG-T" CAPC2012X14N 4705.28,4910.57 r0 top value=10u
C113 "LMK107BJ106MALTD" CAPC1608X09N 1305.58,4021.13 r270 bottom value=10u
C114 "JMK105BBJ475MV-F" CAPC1005X06A#1 1302.99,4039.64 r270 top value=4.7u
C115 "C1005X5R1A335K050BC" CAPC1005X06A#1 1267.58,4027.64 r270 top value=3.3u
C116 "C3216X5R1V226M160AC" CAPC3216N 1168.58,3990.64 r180 bottom value="22 u"
C117 "TMK105BJ104KV-F" CAPC1005X06A#1 1231.58,4027.64 r90 top value="0.1 u"
C118 "C0402C104K8PACTU" CAPC1005X06A#1 1496.58,3689.64 r0 top value="0.1 u"
C119 "C0402C104K8PACTU" CAPC1005X06A#1 1787.58,3732.64 r270 top value="0.1 u"
C120 "LMK316AB7226KL-TR" CAPC3216N 1631.58,3735.64 r270 top value=22u
C121 "LMK316AB7226KL-TR" CAPC3216N 1722.58,3735.64 r270 top value=22u
C122 "SM-0402, 5%, 50v" CAPC1005X06A#1 1480.58,3632.64 r270 top value="56 p"
C123 "C0402C472K5RACTU" CAPC1005X06A#1 1396.66,3560.64 r270 top value="4.7 n"
C124 "C0402C104K8PACTU" CAPC1005X06A#1 1325,3612 r270 top value="0.1 u"
C125 "C0402C220J5GACTU" CAPC1005X06A#1 1360.58,3560.56 r270 top value="22 p"
C126 "C0402C104K8PACTU" CAPC1005X06A#1 1496.58,3980.64 r0 top value="0.1 u"
C127 "C3216X5R1V226M160AC" CAPC3216N 1540.58,3827.64 r90 top value="22 u"
C128 "TMK105BJ104KV-F" CAPC1005X06A#1 1476.58,3827.64 r90 top value="0.1 u"
C129 "C0402C104K8PACTU" CAPC1005X06A#1 1786.58,3917.64 r90 top value="0.1 u"
C130 "LMK316AB7226KL-TR" CAPC3216N 1631.58,3920.64 r90 top value=22u
C131 "LMK316AB7226KL-TR" CAPC3216N 1722.58,3920.64 r90 top value=22u
C132 "C0402C104K8PACTU" CAPC1005X06A#1 1301,4141 r270 top value="0.1 u"
C133 "SM-0402, 5%, 50v" CAPC1005X06A#1 1426.58,4036.64 r0 top value="56 p"
C134 "EEE-FK1E221P" CAPAE9083X70N 875,5033 r0 top value=220u
C135 "TMK105BJ104KV-F" CAPC1005X06A#1 648,5207 r270 top value="0.1 u"
C136 "C0402C472K5RACTU" CAPC1005X06A#1 1337.58,4140.64 r90 top value="4.7 n"
C137 "C0402C220J5GACTU" CAPC1005X06A#1 1372.58,4042.72 r90 top value="22 p"
C138 "C0402C104K8PACTU" CAPC1005X06A#1 1264,4141 r90 top value="0.1 u"
C139 "C0402C104K8PACTU" CAPC1005X06A#1 1106.58,3891.64 r180 top value="0.1 u"
C140 "C3216X5R1V226M160AC" CAPC3216N 1067.58,3831.64 r180 bottom value="22 u"
C141 "TMK105BJ104KV-F" CAPC1005X06A#1 1101.58,3827.64 r180 top value="0.1 u"
C142 "C0402C104K8PACTU" CAPC1005X06A#1 815.58,3907.64 r90 top value="0.1 u"
C143 "LMK316AB7226KL-TR" CAPC3216N 969.58,3925.64 r90 top value=22u
C144 "LMK316AB7226KL-TR" CAPC3216N 878.58,3925.64 r90 top value=22u
C145 "C0402C560J5GACTU" CAPC1005X06A#1 1106.58,3927.64 r180 top value="56 p"
C146 "C0402C104K8PACTU" CAPC1005X06A#1 1198.29,3609.53 r270 top value="0.1 u"
C147 "C0402C472K5RACTU" CAPC1005X06A#1 1177.58,4083.64 r0 top value="4.7 n"
C148 "C0402C220J5GACTU" CAPC1005X06A#1 1195.29,4024.53 r90 top value="22 p"
C149 "C0402C104K8PACTU" CAPC1005X06A#1 1106.98,3768.53 r180 top value="0.1 u"
C150 "C0402C104K8PACTU" CAPC1005X06A#1 815.58,3756.72 r270 top value="0.1 u"
C151 "LMK316AB7226KL-TR" CAPC3216N 969.58,3739.53 r270 top value=22u
C152 "LMK316AB7226KL-TR" CAPC3216N 878.58,3739.64 r270 top value=22u
C153 "C0402C560J5GACTU" CAPC1005X06A#1 1106.98,3731.64 r180 top value="56 p"
C154 "SM-0402, 5%, 50V, NP0" CAPC1005X06A#1 1234.4,3538.16 r90 top value="100 p"
C155 "C0402C472K5RACTU" CAPC1005X06A#1 1146.29,3550.53 r0 top value="4.7 n"
C156 "GJM1555C1H5R0CB01D" CAPC1005X06A#1 1270.4,3538.16 r90 top value="5 p"
C157 "C0402C220J5GACTU" CAPC1005X06A#1 1161.58,3621.64 r270 top value="22 p"
C158 "LMK107BJ106MALTD" CAPC1608X09N 5924.94,4996.77 r0 top value=10u
C159 "LMK107BJ106MALTD" CAPC1608X09N 4269,5689.46 r180 top value=10u
C160 "LMK212BJ106KG-T" CAPC2012X14N 7337,822.98 r180 top value=10u
C161 "C0402C103K4RACTU" CAPC1005X06A#1 5773.94,4914.77 r90 top value="0.01 u"
C162 "LMK107BJ106MALTD" CAPC1608X09N 5817.94,4996.77 r180 top value=10u
C163 "C0402C103K4RACTU" CAPC1005X06A#1 4420,5771.46 r270 top value="0.01 u"
C164 "LMK107BJ106MALTD" CAPC1608X09N 4376,5689.46 r0 top value=10u
C165 "C0402C681K5RACTU" CAPC1005X06A#1 7339,879.48 r180 top value="680 p"
C166 "GJM1555C1H5R0CB01D" CAPC1005X06A#1 7365,1096.48 r90 top value="5 p"
C167 "C0402C103K4RACTU" CAPC1005X06A#1 5976.96,4907.56 r180 top value="0.01 u"
C168 "C0402C103K4RACTU" CAPC1005X06A#1 4216.98,5778.67 r0 top value="0.01 u"
C169 "C0805C226M9PACTU" CAPC2012X14N 7547,1001.48 r90 top value="22 u"
C170 "SM-0402, 10%, 10v" CAPC1005X06A#1 1735.53,878 r90 top value="0.1 u"
C171 "SM-0402, 10%, 10v" CAPC1005X06A#1 1698.53,878 r90 top value="0.1 u"
C172 "SM-0402, 10%, 10v" CAPC1005X06A#1 6673,864 r180 top value="0.1 u"
C173 "SM-0402, 10%, 10v" CAPC1005X06A#1 6673,828 r180 top value="0.1 u"
C174 "C0402C104K8PACTU" CAPC1005X06A#1 6057,5435 r90 top value="0.1 u"
C175 "C0402C104K8PACTU" CAPC1005X06A#1 6093,5435 r90 top value="0.1 u"
C176 "C0805C226M9PACTU" CAPC2012X14N 7471,1001.48 r90 top value="22 u"
C177 "LMK105BJ105KV-F" CAPC1005X06A#1 7231,1018.48 r270 top value=1u
C182 "SM-0402, 10%, 10v" CAPC1005X06A#1 1913.09,879 r90 top value="0.1 u"
C183 "SM-0402, 10%, 10v" CAPC1005X06A#1 1574.53,641 r270 top value="0.1 u"
C185 "SM-0402, 10%, 10v" CAPC1005X06A#1 1877.09,879 r90 top value="0.1 u"
C187 "SM-0402, 10%, 10v" CAPC1005X06A#1 1841.09,879 r90 top value="0.1 u"
C189 "SM-0402, 10%, 10v" CAPC1005X06A#1 1805.09,879 r90 top value="0.1 u"
C190 "C0402C103K4RACTU" CAPC1005X06A#1 2172,416 r180 top value="0.01 u"
C191 "LMK107BJ106MALTD" CAPC1608X09N 6776.83,1172.44 r0 top value=10u
C192 "C0402C104K8PACTU" CAPC1005X06A#1 7122.83,1074.44 r180 top value="0.1 u"
C193 "C0402C104K8PACTU" CAPC1005X06A#1 6719.83,955.44 r0 top value="0.1 u"
C194 "C0402C104K8PACTU" CAPC1005X06A#1 6719.83,1074.44 r0 top value="0.1 u"
C195 "C0402C104K8PACTU" CAPC1005X06A#1 6852.83,1176.44 r270 top value="0.1 u"
C196 "C0402C104K8PACTU" CAPC1005X06A#1 6900.83,1176.44 r270 top value="0.1 u"
C197 "C0402C104K8PACTU" CAPC1005X06A#1 7009,1185 r270 top value="0.1 u"
C198 "C0402C104K8PACTU" CAPC1005X06A#1 7122.83,955.44 r180 top value="0.1 u"
C199 "C0402C104K8PACTU" CAPC1005X06A#1 6900.83,853.44 r90 top value="0.1 u"
C200 "C0402C104K8PACTU" CAPC1005X06A#1 6852.83,853.44 r90 top value="0.1 u"
C201 "C0402C104K8PACTU" CAPC1005X06A#1 7009,840 r90 top value="0.1 u"
C202 "SM-0402, 10%, 10v" CAPC1005X06A#1 7080.83,1203.44 r90 top value="0.1 u"
C203 "SM-0402, 10%, 10v" CAPC1005X06A#1 7080.83,840.44 r90 top value="0.1 u"
C204 "SM-0402, 10%, 10v" CAPC1005X06A#1 6771.53,641 r270 top value="0.1 u"
C205 "SM-0402, 10%, 10v" CAPC1005X06A#1 7044.83,1203.44 r90 top value="0.1 u"
C206 "SM-0402, 10%, 10v" CAPC1005X06A#1 7044.83,840.44 r90 top value="0.1 u"
C207 "SM-0402, 10%, 10v" CAPC1005X06A#1 6972.83,1180.44 r90 top value="0.1 u"
C208 "SM-0402, 10%, 10v" CAPC1005X06A#1 6972.83,849.44 r90 top value="0.1 u"
C209 "SM-0402, 10%, 10v" CAPC1005X06A#1 6936.83,1180.44 r90 top value="0.1 u"
C210 "SM-0402, 10%, 10v" CAPC1005X06A#1 6936.83,849.44 r90 top value="0.1 u"
C211 "C0402C103K4RACTU" CAPC1005X06A#1 7369,468 r180 top value="0.01 u"
D1 "VBUS_FAULT" CD1608-0603-PIN1-CATHODE 5770,5180 r180 top
D2 "Diode" SOD-123 4673.28,4757.57 r180 top
D3 "Diode" SOD-123 4673.28,4676.57 r180 top
D4 "POWER" CD1608-0603-PIN1-CATHODE 1100,4683 r0 top
FB1 "BLM21PG221SN1D" RESC2012N 5794,5653 r180 top value=220
FB2 "HZ0402B102R-10" INDC1005X05N 4495,4914.68 r90 top value="1 k"
FB3 "HZ0805E601R-10" RESC2012N 4491,4801.57 r90 top value=600
FB4 "HZ0805E601R-10" RESC2012N 4610.02,5074.07 r90 top value=600
FID1 "FIDUCIAL" FID1MM/2MM-SS 368,5559 r90 top
FID2 "FIDUCIAL" FID1MM/2MM-SS 8291.17,5499.32 r90 top
FID3 "FIDUCIAL" FID1MM/2MM-SS 8632.5,493.47 r90 top
FID4 "FIDUCIAL" FID1MM/2MM-SS 348,337 r90 top
FID5 "FIDUCIAL" FID1MM/2MM-SS 2405.88,4440.5 r90 bottom
FID6 "FIDUCIAL" FID1MM/2MM-SS 8291.17,5499.32 r90 bottom
FID7 "FIDUCIAL" FID1MM/2MM-SS 8632.5,493.47 r90 bottom
FID8 "FIDUCIAL" FID1MM/2MM-SS 348,337 r90 bottom
J1 "QSE-020-01-F-D-A" QSE-020-01-X-D-A-L 3189.03,5708.66 r180 top locked
J2 "87831-1420" HDR2X7-2MM 8562.63,5088.26 r270 top
J3 "0877584016" HDR2X20-2MM 2755.91,5039.37 r0 top
J4 "0877582016" HDR2X10-2MM 7283.46,5511.81 r0 top
J5 "MDT420M01001" M2-CONNECTOR_M-KEYING 7273.62,1811.02 r90 top locked
J6 "QSH-020-01-F-D-DP-A" QSH-020-01-X-D-DP-A-L 3310.58,196.85 r0 top locked
J7 "QSH-020-01-F-D-DP-A" QSH-020-01-X-D-DP-A-L 5357.82,196.85 r0 top locked
J8 "QSE-020-01-F-D-A" QSE-020-01-X-D-A-L 196.85,1299.26 r270 top locked
J9 "QSE-020-01-F-D-A" QSE-020-01-X-D-A-L 196.85,3149.66 r270 top locked
J10 "0877582016" HDR2X10-2MM 1081.63,2751.37 r90 top
J11 "QSE-020-01-F-D-A" QSE-020-01-X-D-A-L 1338.63,5708.66 r180 top locked
J12 "67800-5005" MOLEX-67800-5005 826.77,196.85 r0 top locked
J13 "0472720001" 0472720001 7913.39,129.92 r0 top locked
J14 "FS1-Z38-20Z6-60" QSFP28_RECEPTACLE_SFF-8679 7401.59,3880.02 r90 top locked
J15 "FS1-Z38-20Z6-60" QSFP28_RECEPTACLE_SFF-8679 7401.58,2663.55 r90 top locked
J16 "1054500101" 1054500101 6268.5,5623.23 r180 top locked
J17 "L829-1J1T-43" L829-1J1T-43 5126,5462.6 r180 top locked
J18 "PJ-102AH" CUI-PJ102A -86.61,5140 r270 top locked
J19 "0455580003" 0455580003 460.63,4506.34 r90 top locked
J20 "0472720001" 0472720001 1732.28,129.92 r0 top locked
J21 "0472720001" 0472720001 6929.13,129.92 r0 top locked
JSO1 "Jack Screw Standoff" JSO-0515-01 2598.42,4389.76 r0 top locked
JSO2 "Jack Screw Standoff" JSO-0515-01 5511.81,4389.76 r0 top locked
JSO3 "Jack Screw Standoff" JSO-0515-01 2598.42,1515.75 r0 top locked
JSO4 "Jack Screw Standoff" JSO-0515-01 5511.81,1515.75 r0 top locked
L1 "XAL6030-222MEB" XAL60XX 1633.58,3503.64 r0 top value=2.2u
L2 "XAL6030-222MEB" XAL60XX 1633.58,4152.64 r0 top value=2.2u
L3 "XAL6030-222MEB" XAL60XX 968.58,4157.64 r180 top value=2.2u
L4 "XAL6030-222MEB" XAL60XX 968.58,3502.64 r180 top value=2.2u
MC1 "QTH-060-01-F-D-A" QTH-060-01-X-D 3661.42,4389.76 r0 top locked
MC2 "QTH-060-01-L-D-DP-A" QTH-060-01-X-D-DP-A 4055.12,1515.75 r0 top locked
MC3 "QTH-090-01-F-D-A" QTH-090-01-X-D 2598.42,2952.76 r90 top locked
MH1 "MTG" MTG-3.2/6.5-PTH 196.85,5708.66 r0 top locked
MH2 "MTG" MTG-3.2/6.5-PTH 8464.57,5708.66 r0 top locked
MH3 "MTG" MTG-3.2/6.5-PTH 8661.42,196.85 r0 top locked
MH4 "MTG" MTG-3.2/6.5-PTH 196.85,196.85 r0 top locked
MH5 "MTG" MTG-3.2/6.5-PTH 4055.12,2952.76 r0 top locked
MH6 "MTG" MTG-2.7/5.0-PTH 2519.69,5708.66 r0 top
MH7 "MTG" MTG-2.7/5.0-PTH 3858.27,5708.66 r0 top
MH8 "MTG" MTG-2.7/5.0-PTH 2566.14,196.85 r0 top
MH9 "MTG" MTG-2.7/5.0-PTH 4055.12,196.85 r0 top
MH10 "MTG" MTG-2.7/5.0-PTH 4613.39,196.85 r0 top
MH11 "MTG" MTG-2.7/5.0-PTH 6102.36,196.85 r0 top
MH12 "MTG" MTG-2.7/5.0-PTH 196.85,629.92 r90 top
MH13 "MTG" MTG-2.7/5.0-PTH 196.85,1968.5 r90 top
MH14 "MTG" MTG-2.7/5.0-PTH 196.85,2480.32 r90 top
MH15 "MTG" MTG-2.7/5.0-PTH 196.85,3818.9 r90 top
MH16 "MTG" MTG-2.7/5.0-PTH 669.29,5708.66 r0 top
MH17 "MTG" MTG-2.7/5.0-PTH 2007.87,5708.66 r0 top
Q1 "2.2A, 30V" SOT23-95P240X110 1065.7,4516.67 r0 top
QSFP1 "U95-T111-1001" QSFP28_SINGLE_CAGE 7401.59,3880.02 r90 top locked
QSFP2 "U95-T111-1001" QSFP28_SINGLE_CAGE 7401.58,2663.55 r90 top locked
R1 "CRCW040234K0FKED" RESC1005X06A#1 3462,5496 r90 top value="34 k"
R2 "CRCW040210K0FKED" RESC1005X06A#2 8091,4897 r0 top value="10.0 k"
R3 "CRCW040210K0FKED" RESC1005X06A#2 8091,4976 r0 top value="10.0 k"
R4 "CRCW040210K0FKED" RESC1005X06A#2 8091,5056 r0 top value="10.0 k"
R5 "CRCW040210K0FKED" RESC1005X06A#2 8091,4861 r180 top value="10.0 k"
R6 "CRCW040210K0FKED" RESC1005X06A#2 8091,4940 r180 top value="10.0 k"
R7 "CRCW040210K0FKED" RESC1005X06A#2 8091,5020 r180 top value="10.0 k"
R8 "CRCW040210K0FKED" RESC1005X06A#2 6842.6,1407.15 r0 top value="10.0 k"
R9 "CRCW040210K0FKED" RESC1005X06A#2 6842.6,1481.15 r0 top value="10.0 k"
R10 "CRCW040210K0FKED" RESC1005X06A#2 6842.6,1555.15 r0 top value="10.0 k"
R11 "CRCW040210K0FKED" RESC1005X06A#2 6842.6,1444.15 r180 top value="10.0 k"
R12 "CRCW040210K0FKED" RESC1005X06A#2 6842.6,1518.15 r180 top value="10.0 k"
R13 "CRCW040210K0FKED" RESC1005X06A#2 6842.6,1592.15 r180 top value="10.0 k"
R14 "CRCW040224K9FKED" RESC1005X06A#1 3045,410 r270 top value="24.9 k"
R15 "CRCW040218K7FKED" RESC1005X06A#2 5093,410 r270 top value=18.7k
R16 "CRCW0402210KFKED" RESC1005X06A#1 410,1567 r180 top value="210 k"
R17 "CRCW040284K5FKED" RESC1005X06A#1 410,3426 r180 top value="84.5 k"
R18 "CRCW040249K9FKED" RESC1005X06A#1 1606,5495 r90 top value=49.9k
R19 "CRCW04020000Z0ED" RESC1005X06A#1 7833.77,1307.26 r90 top value=0
R20 "CRCW04020000Z0ED" RESC1005X06A#1 7797.77,1307.26 r90 top value=0
R21 "CRCW04020000Z0ED" RESC1005X06A#1 7761.77,1307.26 r90 top value=0
R22 "CRCW04020000Z0ED" RESC1005X06A#1 7725.77,1307.26 r90 top value=0
R23 "CRCW04021M00FKEDC" RESC1005X06A#1 7587,1235 r90 top value="1 M"
R24 "CRCW04021M00FKEDC" RESC1005X06A#1 7690,905 r0 top value="1 M"
R25 "CRCW04021M00FKEDC" RESC1005X06A#1 7587,1163 r90 top value="1 M"
R26 "CRCW04021M00FKEDC" RESC1005X06A#1 7690,1014 r180 top value="1 M"
R27 "CRCW04021M00FKEDC" RESC1005X06A#1 8354,459 r180 top value="1 M"
R28 "CRCW04021M00FKEDC" RESC1005X06A#1 7713.53,697 r0 top value="1 M"
R29 "CRCW04021M00FKEDC" RESC1005X06A#1 7713.53,660 r0 top value="1 M"
R30 "CRCW040210K0FKED" RESC1005X06A#1 7976.77,942.26 r270 top value="10.0 k"
R31 "CRCW040210K0FKED" RESC1005X06A#1 8052.77,942.26 r270 top value="10.0 k"
R32 "CRCW040210K0FKED" RESC1005X06A#1 8128.77,942.26 r270 top value="10.0 k"
R33 "CRCW040210K0FKED" RESC1005X06A#1 8204.77,942.26 r270 top value="10.0 k"
R34 "CRCW040210K0FKED" RESC1005X06A#1 8280.77,942.26 r270 top value="10.0 k"
R35 "CRCW0402100KFKED" RESC1005X06A#1 7713.53,771 r180 top value="100 k"
R36 "CRCW040210K0FKED" RESC1005X06A#1 8014.77,942.26 r90 top value="10.0 k"
R37 "CRCW040210K0FKED" RESC1005X06A#1 8090.77,942.26 r90 top value="10.0 k"
R38 "CRCW040210K0FKED" RESC1005X06A#1 8166.77,942.26 r90 top value="10.0 k"
R39 "CRCW040210K0FKED" RESC1005X06A#1 8242.77,942.26 r90 top value="10.0 k"
R40 "CRCW040210K0FKED" RESC1005X06A#1 8318.77,942.26 r90 top value="10.0 k"
R41 "CRCW06030000Z0EA" RESC1608N 6691.8,4219.72 r270 top value=0
R42 "CRCW06030000Z0EA" RESC1608N 6694.01,4379.65 r270 top value=0
R43 "CRCW06030000Z0EA" RESC1608N 6691.8,4084.72 r270 top value=0
R44 "CRCW04024K70JNED" RESC1005X06A#2 6549,3857.7 r270 top value="4.7 k"
R45 "CRCW04024K70JNED" RESC1005X06A#1 5672.46,3440.65 r0 top value="4.7 k"
R46 "CRCW04020000Z0ED" RESC1005X06A#2 6587,3857.7 r90 top value=0
R47 "CRCW04020000Z0ED" RESC1005X06A#2 6644,3857.7 r90 top value=0
R48 "CRCW04024K70JNED" RESC1005X06A#1 5673.46,3662.65 r0 top value="4.7 k"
